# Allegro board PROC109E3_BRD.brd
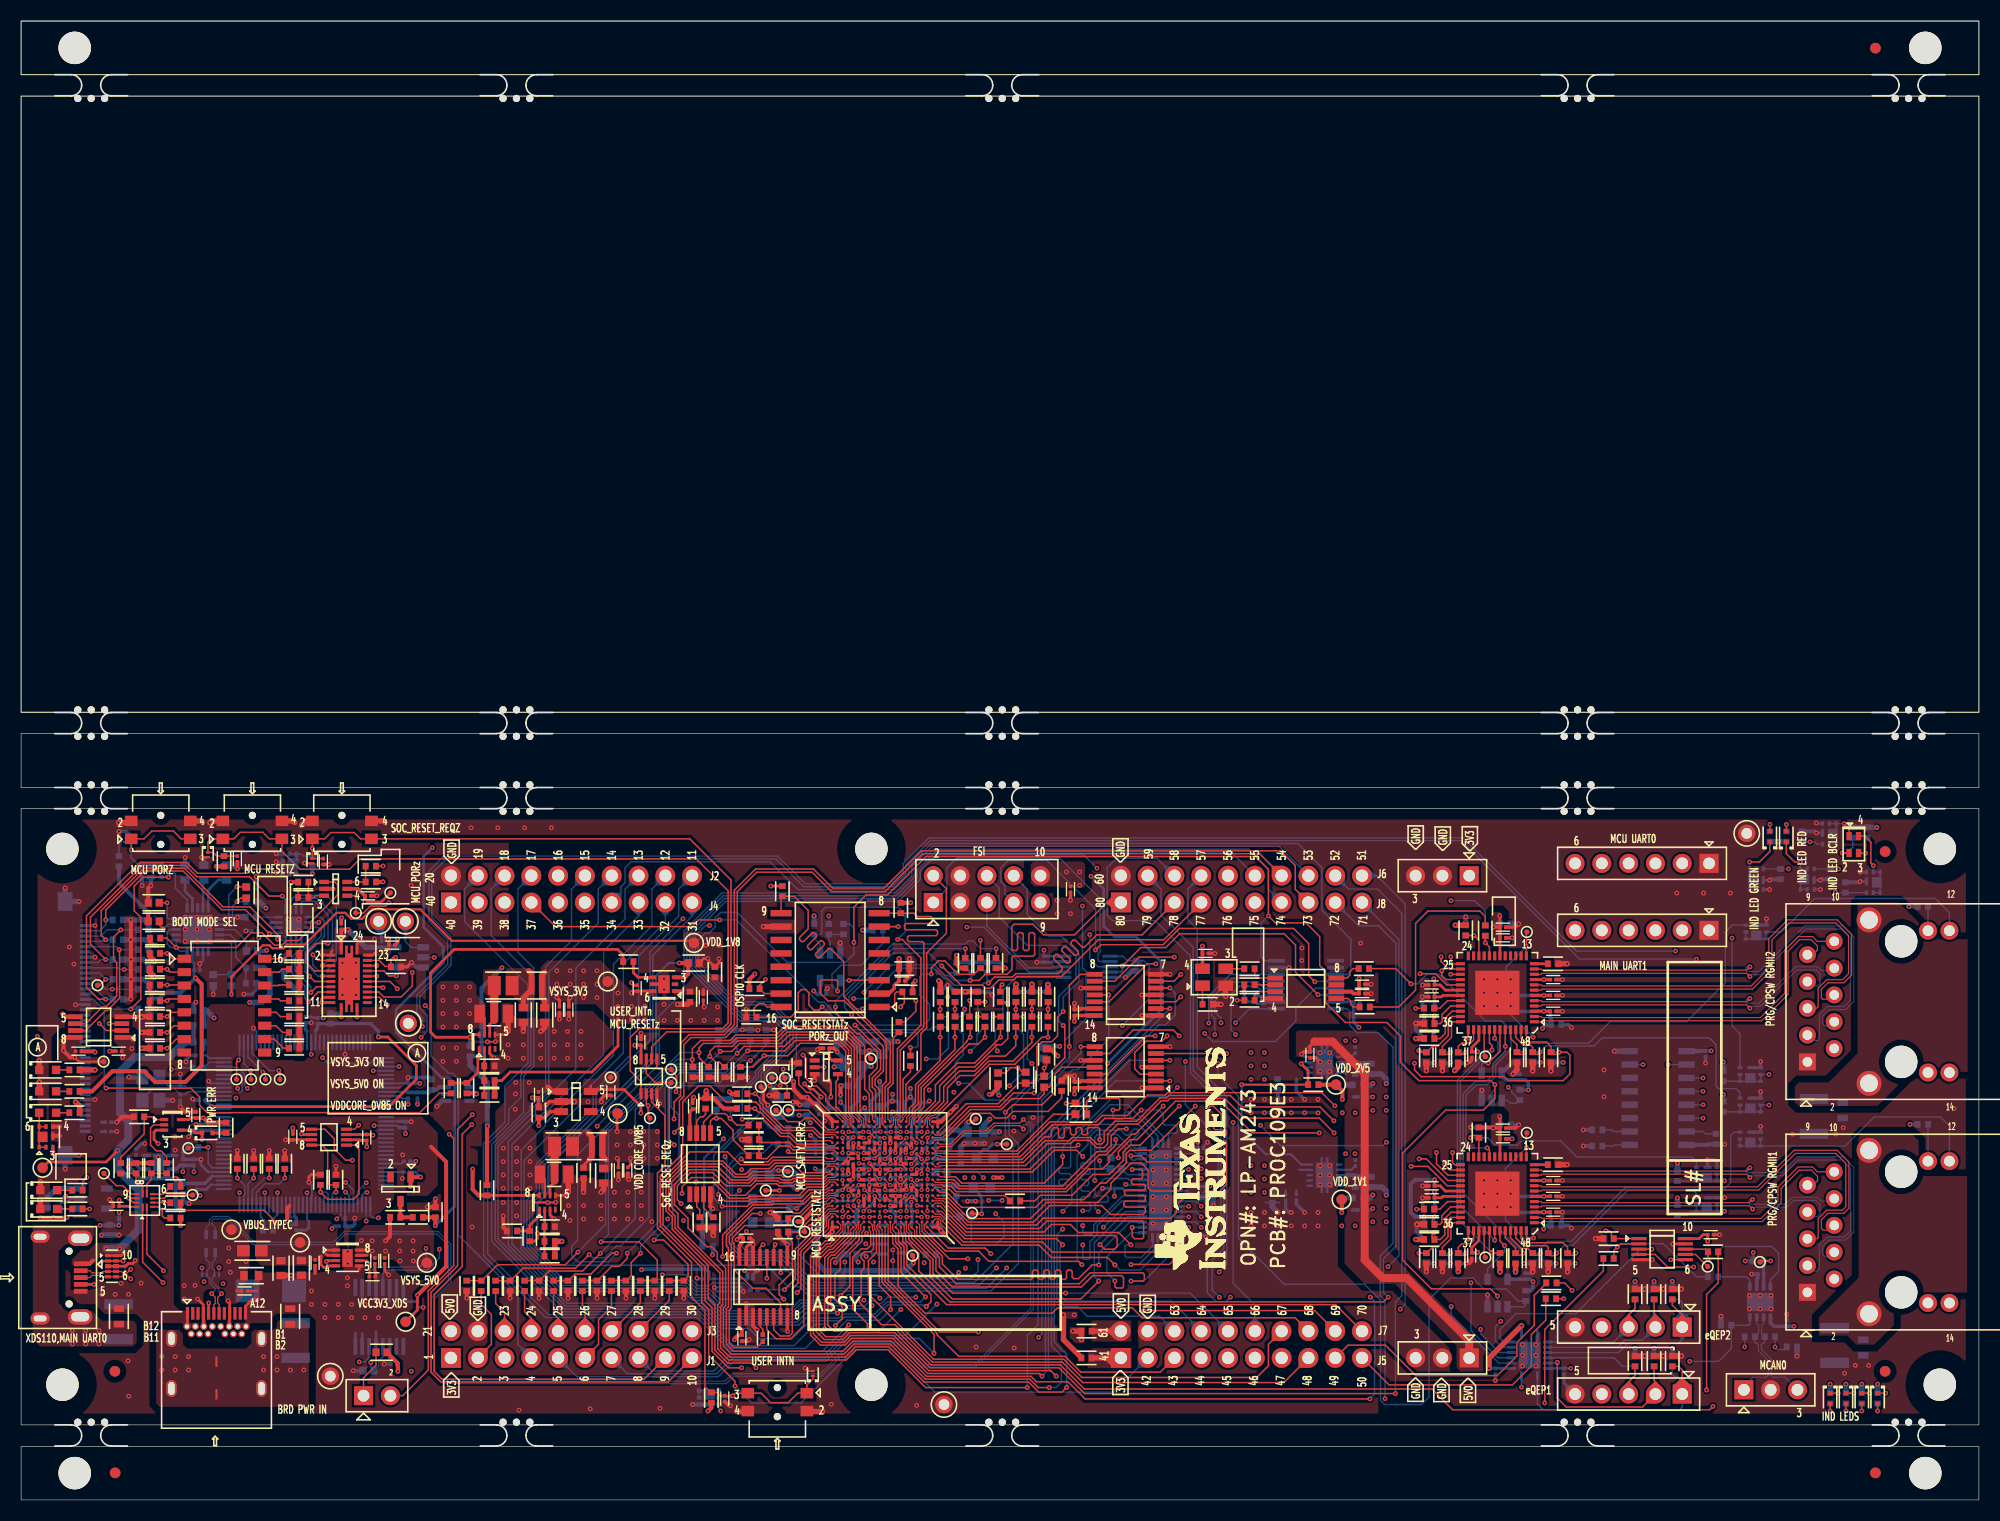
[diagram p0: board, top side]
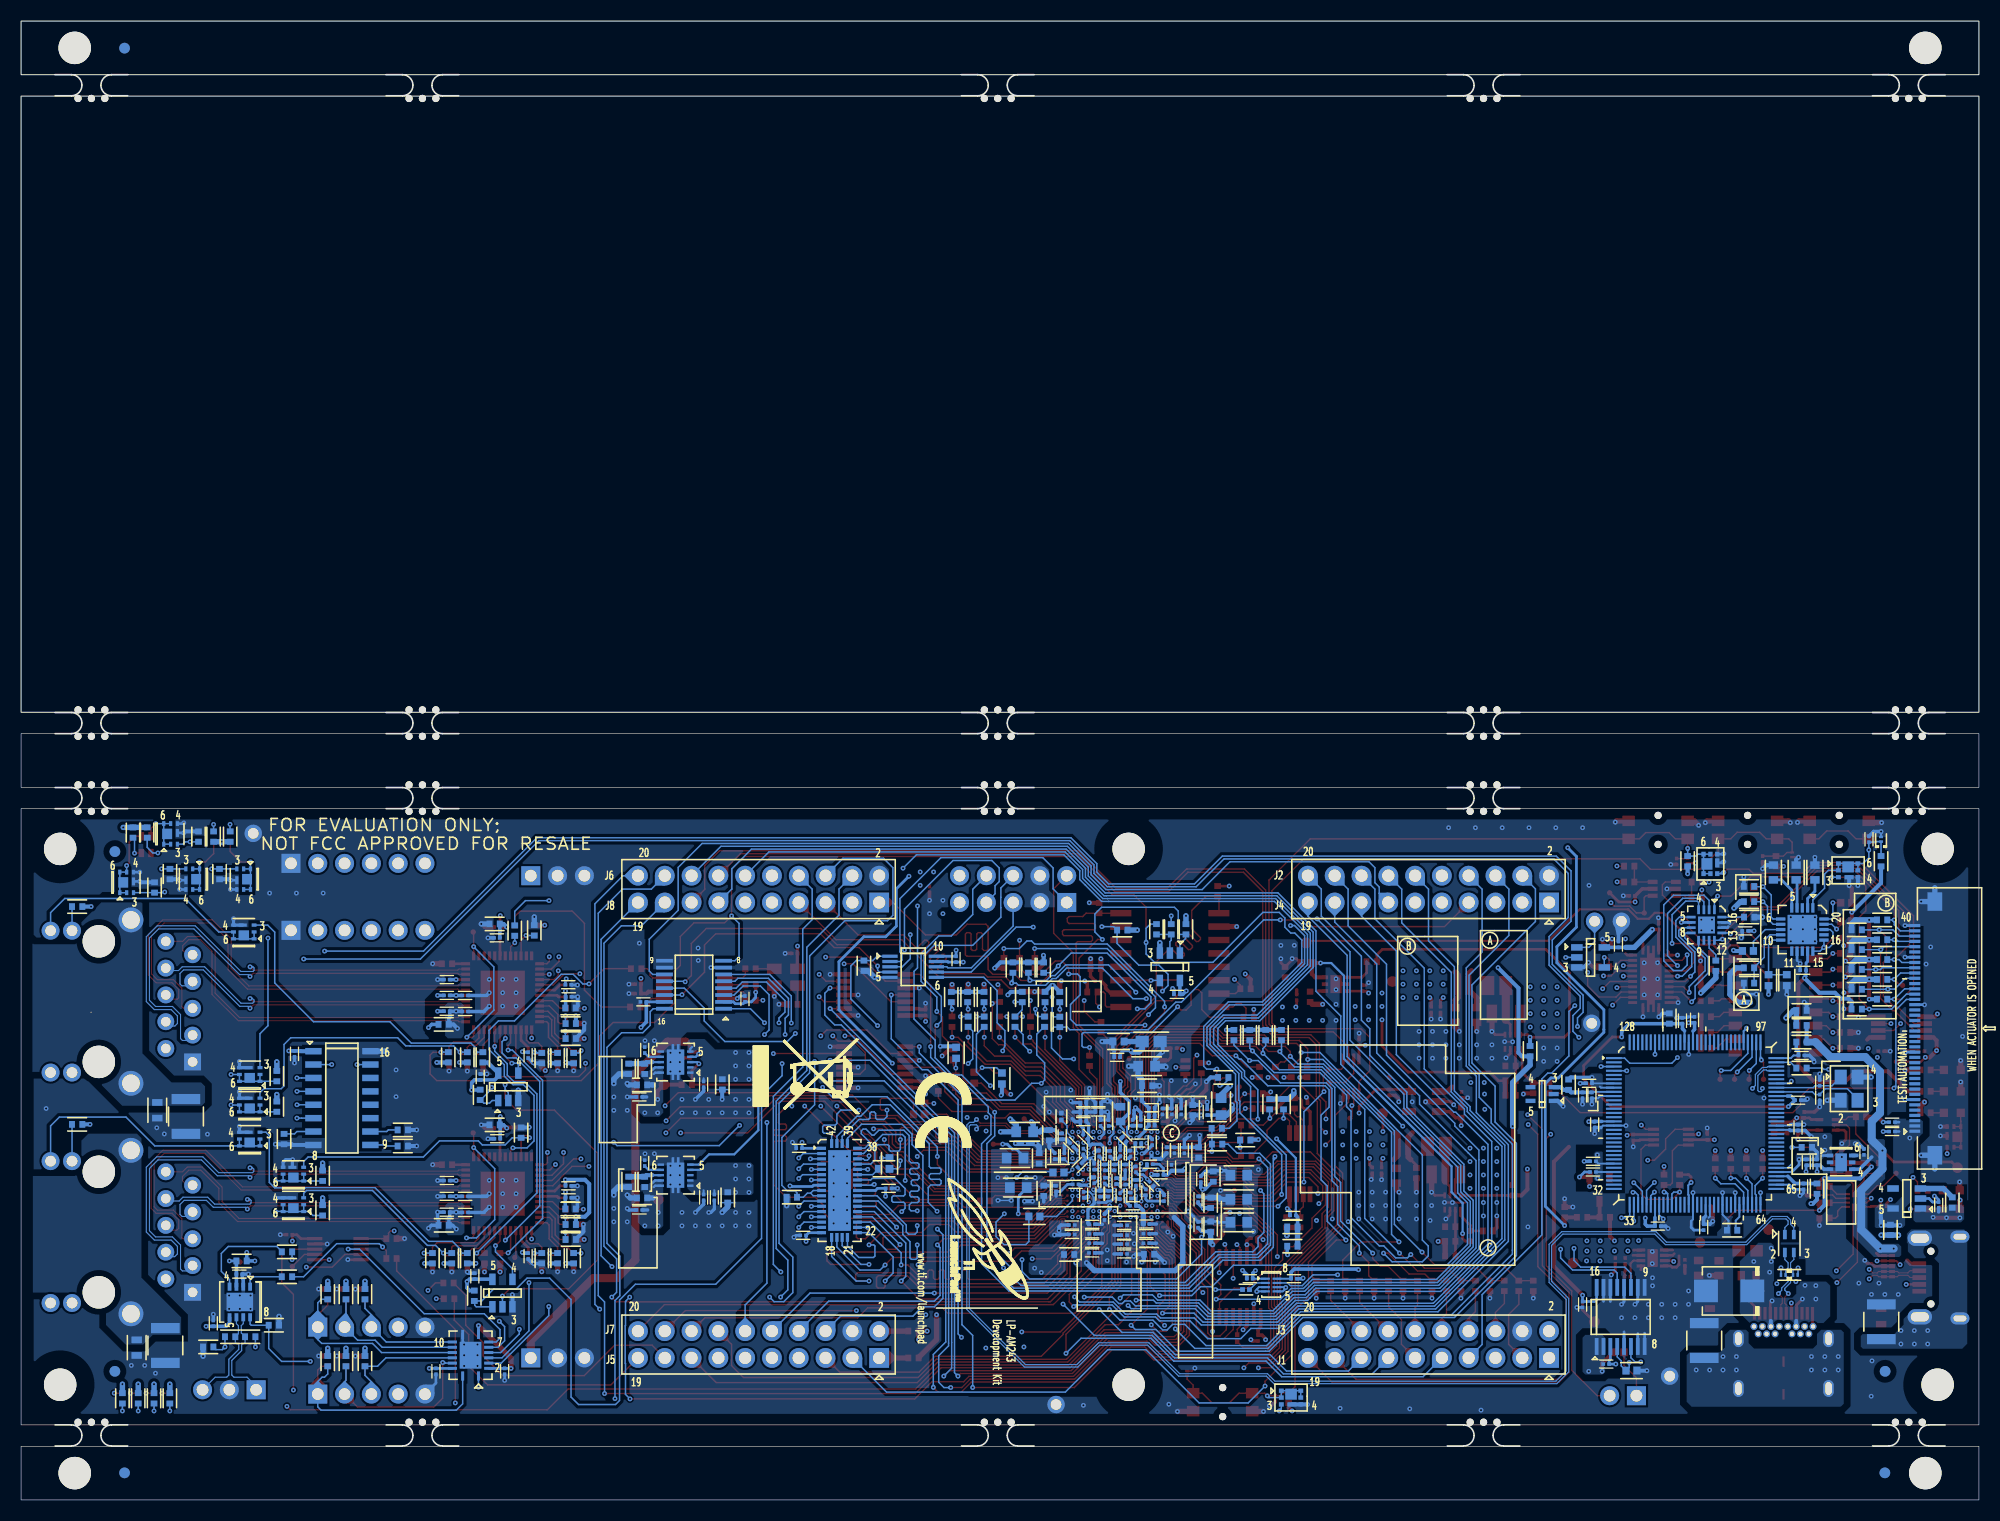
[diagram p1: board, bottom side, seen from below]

Outline 185.58 x 140.21 mm; copper layers: TOP, L02_GND1, L03_SIG1, L04_PWR1, L05_GND2, BOTTOM. Coordinates in mm from the lower left corner of the outline.
Outline path: rectangle 0,135.13 185.58,140.21 ; rectangle 0,74.68 185.58,133.1 ; 0,72.64 0,67.56 185.58,67.56 185.58,72.64 0,72.64 ; 0,65.53 0,7.11 185.58,7.11 185.58,65.53 0,65.53 ; 0,5.08 0,0 185.58,0 185.58,5.08 0,5.08

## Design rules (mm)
net group MCAN0_HL: nets MCAN0_H MCAN0_L
net group PRG1_CPSW_RGMII2_RX: nets PRG1_CPSW_RGMII2_RD0 PRG1_CPSW_RGMII2_RD1
net group TYPEC_DP: nets TYPEC_DN TYPEC_DP
net group USB0: nets USB0_DN USB0_DP
net group XDS_USB_D_NP: nets XDS_USB_D_N XDS_USB_D_P
net group CPSW_RGMII1_TD1: nets CPSW_RGMII1_TD1
net group CPSW_RGMII1_TX_CTL: nets CPSW_RGMII1_TX_CTL
net group PRG1_CPSW RGMII2_TX: nets PRG1_CPSW_RGMII2_TD0 PRG1_CPSW_RGMII2_TD1 PRG1_CPSW_RGMII2_TD2 PRG1_CPSW_RGMII2_TD3 PRG1_CPSW_RGMII2_TX_CTL
net group PRG1_CPSW_RGMII1_RXC: nets PRG1_CPSW_RGMII1_RXC
net group PRG1_CPSW_RGMII2_RXC: nets PRG1_CPSW_RGMII2_RXC
net group PRG1_CPSW_RGMII2_TXC: nets PRG1_CPSW_RGMII2_TXC
net group PWR\GND: nets VBAT_XDS VCC_5V0_CAN VDD_1V1_SS VDD_1V8_R VDD_2V5_PG VDD_CORE_0V85_R VDDA_3V3 VDDA_PLL0 VDDC_1V2_XDS VDDSHV_SDIO VMON_VSYS VSYS_3V3_R XDS_VREF

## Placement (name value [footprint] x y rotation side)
C1  1uF  [CAP0201_0-5]  20.5 60.76 270 top
C2  1uF  [CAP0201_0-5]  28.65 60.53 270 top
C3  0.1uF  [CAP0201_0-5]  99.47 57.89 90 top
C4  0.1uF  [CAP0201_0-5]  32.87 57.28 0 top
C5  0.1uF  [CAP0201_0-5]  30.34 54.36 90 top
C6  0.1uF  [CAP0201_0-5]  140.46 54.31 0 top
C7  0.1uF  [CAP0201_0-5]  140.46 53.29 0 top
C8  0.1uF  [CAP0201_0-5]  35.15 52.6 0 top
C9  0.1uF  [CAP0201_0-5]  112.26 51.82 180 top
C10  4.7uF  [CAP0402_0-75]  83.72 50.37 0 top
C11  0.1uF  [CAP0201_0-5]  145.23 49.33 0 top
C12  0.1uF  [CAP0201_0-5]  83.49 49.2 0 top
C13  1uF  [CAP0201_0-5]  127.11 48.9 0 top
C14  0.01uF  [CAP0201_0-5]  133.7 48.83 180 top
C15  1uF  [CAP0201_0-5]  58.4 48.51 90 top
C16  0.1uF  [CAP0201_0-5]  127.11 48.01 180 top
C17  0.01uF  [CAP0201_0-5]  145.23 47.83 0 top
C18  2.2uF  [CAP0402_0-75]  63.4 47.7 270 top
C19  0.1uF  [CAP0201_0-5]  133.7 47.69 180 top
C20  0.1uF  [CAP0201_0-5]  64.67 47.65 270 top
C21  0.1uF  [CAP0201_0-5]  51.03 46.48 270 top
C22  0.1uF  [CAP0201_0-5]  51.92 46.48 270 top
C23  0.01uF  [CAP0201_0-5]  145.23 46.33 0 top
C24  0.1uF  [CAP0201_0-5]  99.84 46.21 90 top
C25  4.7uF  [CAP1206_2]  44.81 46.1 0 top
C26  22uF  [CAP0603_1]  47.6 45.97 270 top
C27  47uF  [CAP0603_1]  49.64 45.97 270 top
C28  100pF  [CAP0402_0-75]  63.68 40.56 270 top
C29  0.1uF  [CAP0201_0-5]  58.75 43.38 90 top
C30  0.1uF  [CAP0201_0-5]  76.33 42.82 0 top
C31  0.1uF  [CAP0201_0-5]  5.44 42.55 0 top
C32  0.1uF  [CAP0201_0-5]  9.25 42.55 180 top
C33  100pF  [CAP0402_0-75]  65.18 40.56 270 top
C34  0.1uF  [CAP0201_0-5]  137.51 42.22 270 top
C35  100pF  [CAP0402_0-75]  66.69 40.56 270 top
C36  100pF  [CAP0402_0-75]  68.19 40.56 270 top
C37  0.1uF  [CAP0201_0-5]  99.84 39.35 90 top
C38  1uF  [CAP0201_0-5]  55.91 38.63 270 top
C39  1uF  [CAP0201_0-5]  49.05 38.4 270 top
C40  120pF  [CAP0402_0-75]  44.39 38.35 180 top
C41  0.1uF  [CAP0201_0-5]  63.65 37.34 90 top
C42  0.1uF  [CAP0201_0-5]  16.56 36.5 90 top
C43  0.1uF  [CAP0201_0-5]  140.46 35.26 0 top
C44  0.1uF  [CAP0201_0-5]  25.76 34.42 90 top
C45  0.1uF  [CAP0201_0-5]  32.77 34.36 270 top
C46  0.1uF  [CAP0201_0-5]  140.46 34.24 0 top
C47  10pF  [CAP0402_0-75]  69.45 34.16 180 top
C48  0.1uF  [CAP0201_0-5]  56.62 31.24 270 top
C49  0.1uF  [CAP0201_0-5]  57.51 31.24 270 top
C50  10uF  [CAP0402_0-75]  53.32 30.99 270 top
C51  4.7uF  [CAP1206_2]  50.53 30.86 0 top
C52  47uF  [CAP0603_1]  55.22 30.73 270 top
C53  0.1uF  [CAP0201_0-5]  145.23 30.28 0 top
C54  0.01uF  [CAP0201_0-5]  133.7 29.78 180 top
C55  0.01uF  [CAP0201_0-5]  145.23 28.78 0 top
C56  0.1uF  [CAP0201_0-5]  133.7 28.64 180 top
C57  0.1uF  [CAP0201_0-5]  9.02 27.84 180 top
C58  0.01uF  [CAP0201_0-5]  145.23 27.28 0 top
C59  0.1uF  [CAP0201_0-5]  160.15 25.15 0 top
C60  0.1uF  [CAP0201_0-5]  68.73 24.82 0 top
C61  0.1uF  [CAP0201_0-5]  137.51 23.17 270 top
C62  120pF  [CAP0402_0-75]  50.11 23.11 180 top
C63  0.1uF  [CAP0201_0-5]  33.53 22.66 270 top
C64  1uF  [CAP0201_0-5]  34.47 22.66 270 top
C65  0.1uF  [CAP0201_0-5]  27.86 22.48 270 top
C66  10uF  [CAP0603_1]  26.57 22 270 top
C67  10uF  [CAP0603_1]  24.64 21.97 270 top
C68  10uF  [CAP0603_1]  21.82 21.26 0 top
C69  0.01uF  [CAP0201_0-5]  33.3 21.16 0 top
C70  0.1uF  [CAP0201_0-5]  21.19 19.81 0 top
C71  1000pF  [CAP0402_0-75]  152.98 19.51 90 top
C72  1000pF  [CAP0402_0-75]  154.79 19.51 90 top
C73  1000pF  [CAP0402_0-75]  156.51 19.51 90 top
C74  0.1uF  [CAP0201_0-5]  68.33 15.34 270 top
C75  1000pF  [CAP0402_0-75]  152.98 13.16 90 top
C76  1000pF  [CAP0402_0-75]  154.79 13.16 90 top
C77  1000pF  [CAP0402_0-75]  156.51 13.16 90 top
C78  1uF  [CAP0201_0-5]  66.7 9.61 270 top
C79  1uF  [CAP0201_0-5]  10.42 62.64 90 bottom
C80  2400pF  [CAP0603_1]  19.48 59.49 90 bottom
C81  2400pF  [CAP0603_1]  17.32 59.49 90 bottom
C82  2400pF  [CAP0603_1]  15.54 59.49 90 bottom
C84  10uF  [CAP0402_0-75]  140.7 54.61 0 bottom
C85  0.1uF  [CAP0201_0-5]  22.15 53.95 180 bottom
C86  1uF  [CAP0201_0-5]  140.49 53.29 0 bottom
C88  0.1uF  [CAP0201_0-5]  34.17 52.66 90 bottom
C90  0.1uF  [CAP0201_0-5]  96.96 51.27 270 bottom
C91  0.1uF  [CAP0201_0-5]  16.66 50.22 0 bottom
C92  0.1uF  [CAP0201_0-5]  145.23 49.33 0 bottom
C93  1uF  [CAP0201_0-5]  133.71 48.84 180 bottom
C94  0.1uF  [CAP0201_0-5]  76.02 47.93 0 bottom
C95  0.1uF  [CAP0201_0-5]  145.23 47.83 0 bottom
C96  1uF  [CAP0201_0-5]  143.49 47.83 180 bottom
C97  1uF  [CAP0201_0-5]  133.68 47.7 180 bottom
C98  10uF  [CAP0402_0-75]  133.51 46.63 180 bottom
C99  1uF  [CAP0201_0-5]  145.23 46.33 0 bottom
C100  1uF  [CAP0201_0-5]  143.49 46.3 180 bottom
C101  1000pF  [CAP1210_1-5]  169.95 36.36 270 bottom
C102  2.2uF  [CAP0402_0-75]  29.34 45.64 90 bottom
C103  0.1uF  [CAP0201_0-5]  116.97 47.5 90 bottom
C104  0.1uF  [CAP0201_0-5]  26.95 45.52 90 bottom
C105  0.01uF  [CAP0201_0-5]  28.1 45.43 90 bottom
C106  0.1uF  [CAP0201_0-5]  126.59 47.22 0 bottom
C107  10uF  [CAP0402_0-75]  145.52 45.09 0 bottom
C108  100pF  [CAP0402_0-75]  66.11 44.07 90 bottom
C109  4.7uF  [CAP0402_0-75]  81.56 43.46 0 bottom
C110  100pF  [CAP0402_0-75]  67.61 44.07 90 bottom
C111  0.01uF  [CAP0201_0-5]  126.47 42.65 90 bottom
C112  0.1uF  [CAP0201_0-5]  159.66 42.29 90 bottom
C113  1uF  [CAP0201_0-5]  137.52 42.16 270 bottom
C114  0.1uF  [CAP0201_0-5]  16.82 42.14 180 bottom
C116  0.01uF  [CAP0201_0-5]  81.69 41.96 0 bottom
C117  100pF  [CAP0402_0-75]  69.11 44.07 90 bottom
C118  100pF  [CAP0402_0-75]  70.62 44.07 90 bottom
C119  0.1uF  [CAP0201_0-5]  142.06 40.11 90 bottom
C120  30pF  [CAP0201_0-5]  15.09 39.55 270 bottom
C121  0.1uF  [CAP0201_0-5]  36.96 39.5 0 bottom
C122  0.1uF  [CAP0201_0-5]  120.88 39.4 270 bottom
C123  1uF  [CAP0201_0-5]  122.17 42.19 270 top
C124  4.7uF  [CAP0402_0-75]  119.11 39.4 270 bottom
C125  10uF  [CAP0402_0-75]  126.72 39.35 0 bottom
C126  4.7uF  [CAP0402_0-75]  78.84 39.27 180 bottom
C128  0.01uF  [CAP0201_0-5]  37.57 38.35 270 bottom
C129  0.1uF  [CAP0201_0-5]  36.68 38.35 270 bottom
C130  0.1uF  [CAP0201_0-5]  126.97 38.21 0 bottom
C131  30pF  [CAP0201_0-5]  15.09 38.15 90 bottom
C132  1uF  [CAP0201_0-5]  17.14 37.9 180 bottom
C133  0.1uF  [CAP0201_0-5]  84.89 37.67 0 bottom
C134  0.1uF  [CAP0201_0-5]  83.47 37.67 180 bottom
C135  0.1uF  [CAP0201_0-5]  78.41 37.19 180 bottom
C136  10uF  [CAP0402_0-75]  74.52 36.96 90 bottom
C137  0.1uF  [CAP0201_0-5]  77.39 36.83 90 bottom
C138  0.1uF  [CAP0201_0-5]  76.5 36.83 90 bottom
C139  0.1uF  [CAP0201_0-5]  75.62 36.83 90 bottom
C140  0.1uF  [CAP0201_0-5]  84.89 36.78 0 bottom
C141  0.1uF  [CAP0201_0-5]  83.47 36.78 180 bottom
C142  0.1uF  [CAP0201_0-5]  73.15 36.77 90 bottom
C143  3.3uF  [CAP0603_1]  81.36 36.58 90 bottom
C144  0.1uF  [CAP0201_0-5]  78.41 36.42 180 bottom
C145  0.1uF  [CAP0201_0-5]  84.89 35.86 0 bottom
C146  0.1uF  [CAP0201_0-5]  8.23 35.81 0 bottom
C147  0.1uF  [CAP0201_0-5]  80.21 35.76 90 bottom
C148  0.01uF  [CAP0201_0-5]  79.45 35.76 90 bottom
C149  1uF  [CAP0201_0-5]  83.26 35.74 90 bottom
C150  1uF  [CAP0201_0-5]  82.5 35.74 90 bottom
C151  0.01uF  [CAP0201_0-5]  36.42 35.59 270 bottom
C152  10uF  [CAP0402_0-75]  140.7 35.56 0 bottom
C153  0.01uF  [CAP0201_0-5]  78.41 35.48 180 bottom
C154  1uF  [CAP0201_0-5]  17.14 35.31 90 bottom
C155  0.1uF  [CAP0201_0-5]  8.23 34.92 0 bottom
C156  4.7uF  [CAP0402_0-75]  88.11 34.57 270 bottom
C157  0.1uF  [CAP0201_0-5]  86.89 34.47 270 bottom
C158  0.1uF  [CAP0201_0-5]  84.71 34.42 45 bottom
C159  1uF  [CAP0201_0-5]  140.44 34.24 0 bottom
C160  0.1uF  [CAP0201_0-5]  81 34.19 225 bottom
C161  10pF  [CAP0402_0-75]  69.55 34.11 180 bottom
C162  0.1uF  [CAP0201_0-5]  78.36 33.91 90 bottom
C163  0.1uF  [CAP0201_0-5]  79.68 33.83 180 bottom
C165  0.1uF  [CAP0201_0-5]  86.03 33.68 45 bottom
C166  0.1uF  [CAP0201_0-5]  111.83 33.34 0 bottom
C167  0.1uF  [CAP0201_0-5]  77.01 33.15 90 bottom
C168  0.1uF  [CAP0201_0-5]  76.26 33.15 90 bottom
C169  0.1uF  [CAP0201_0-5]  75.32 33.15 90 bottom
C170  1uF  [CAP0201_0-5]  10.9 32.99 90 bottom
C171  4.7uF  [CAP0402_0-75]  73.97 32.94 90 bottom
C172  0.1uF  [CAP0201_0-5]  81.39 32.87 270 bottom
C173  1uF  [CAP0201_0-5]  83.39 32.84 270 bottom
C174  0.01uF  [CAP0201_0-5]  80.42 32.84 90 bottom
C175  0.1uF  [CAP0201_0-5]  82.35 32.82 270 bottom
C176  0.1uF  [CAP0201_0-5]  87.6 32.59 90 bottom
C177  0.01uF  [CAP0201_0-5]  86.69 32.59 90 bottom
C178  0.01uF  [CAP0201_0-5]  84.89 33.02 270 bottom
C179  4.7uF  [CAP0402_0-75]  89.08 32.38 90 bottom
C180  1uF  [CAP0201_0-5]  36.58 32.11 0 bottom
C181  0.1uF  [CAP0201_0-5]  16.36 32 270 bottom
C182  1uF  [CAP0201_0-5]  15.35 32 270 bottom
C183  0.01uF  [CAP0201_0-5]  126.47 31.93 90 bottom
C184  0.01uF  [CAP0201_0-5]  78.59 31.83 180 bottom
C185  0.01uF  [CAP0201_0-5]  83.87 31.6 90 bottom
C186  0.1uF  [CAP0201_0-5]  82.87 31.52 270 bottom
C187  1uF  [CAP0201_0-5]  81.92 31.52 270 bottom
C188  0.01uF  [CAP0201_0-5]  80.91 31.52 270 bottom
C189  0.1uF  [CAP0201_0-5]  76.53 31.5 270 bottom
C190  0.01uF  [CAP0201_0-5]  79.91 31.34 270 bottom
C191  0.01uF  [CAP0201_0-5]  36.58 31.09 0 bottom
C192  1uF  [CAP0201_0-5]  77.57 30.82 180 bottom
C193  4.7uF  [CAP0402_0-75]  72.57 30.66 270 bottom
C194  0.1uF  [CAP0201_0-5]  73.76 30.4 270 bottom
C196  1uF  [CAP0201_0-5]  83.86 30.3 270 bottom
C197  0.1uF  [CAP0201_0-5]  145.23 30.28 0 bottom
C198  0.01uF  [CAP0201_0-5]  82.85 30.28 270 bottom
C199  0.1uF  [CAP0201_0-5]  81.79 30.23 90 bottom
C200  0.01uF  [CAP0201_0-5]  80.92 30.18 90 bottom
C201  0.1uF  [CAP0201_0-5]  79.91 30.06 270 bottom
C202  0.1uF  [CAP0201_0-5]  78.41 29.97 45 bottom
C203  0.01uF  [CAP0201_0-5]  85.62 29.92 0 bottom
C204  0.1uF  [CAP0201_0-5]  87.48 29.51 270 bottom
C205  0.1uF  [CAP0201_0-5]  85.24 31.75 135 bottom
C206  4.7uF  [CAP0402_0-75]  88.65 29.31 270 bottom
C207  1uF  [CAP0201_0-5]  133.7 29.78 180 bottom
C208  0.1uF  [CAP0201_0-5]  16.62 29.72 270 bottom
C209  0.1uF  [CAP0201_0-5]  103.35 29.54 180 bottom
C210  0.01uF  [CAP0201_0-5]  78.97 29.16 270 bottom
C211  0.1uF  [CAP0201_0-5]  83.32 29.03 270 bottom
C212  0.1uF  [CAP0201_0-5]  82.5 29.03 270 bottom
C213  0.1uF  [CAP0201_0-5]  84.86 28.93 270 bottom
C214  0.1uF  [CAP0201_0-5]  80.39 28.85 90 bottom
C215  0.1uF  [CAP0201_0-5]  81.41 28.8 90 bottom
C216  0.1uF  [CAP0201_0-5]  145.23 28.78 0 bottom
C217  1uF  [CAP0201_0-5]  143.49 28.78 180 bottom
C218  0.1uF  [CAP0201_0-5]  120.88 28.68 270 bottom
C219  1uF  [CAP0201_0-5]  119.87 28.68 270 bottom
C220  4.7uF  [CAP0402_0-75]  118.6 28.68 270 bottom
C221  1uF  [CAP0201_0-5]  133.7 28.64 180 bottom
C222  10uF  [CAP0402_0-75]  126.72 28.63 0 bottom
C223  1uF  [CAP0201_0-5]  77.24 28.6 270 bottom
C224  0.1uF  [CAP0201_0-5]  74.02 28.5 270 bottom
C225  4.7uF  [CAP0402_0-75]  72.82 28.17 270 bottom
C226  1uF  [CAP0201_0-5]  3.81 27.96 90 bottom
C227  0.1uF  [CAP0201_0-5]  80.19 27.89 0 bottom
C228  10uF  [CAP0402_0-75]  133.51 27.58 180 bottom
C229  0.1uF  [CAP0201_0-5]  126.97 27.49 0 bottom
C230  1uF  [CAP0201_0-5]  145.23 27.28 0 bottom
C231  1uF  [CAP0201_0-5]  143.49 27.25 180 bottom
C232  0.1uF  [CAP0201_0-5]  65.02 26.97 0 bottom
C233  1uF  [CAP0201_0-5]  82.88 26.82 270 bottom
C234  0.01uF  [CAP0201_0-5]  78.92 26.16 180 bottom
C235  0.1uF  [CAP0201_0-5]  84.05 26.13 180 bottom
C236  0.1uF  [CAP0201_0-5]  74.02 26.09 270 bottom
C237  0.1uF  [CAP0201_0-5]  85.98 26.06 0 bottom
C238  10uF  [CAP0402_0-75]  145.52 26.03 0 bottom
C239  0.1uF  [CAP0201_0-5]  81.03 26.03 0 bottom
C240  0.01uF  [CAP0201_0-5]  30.43 25.96 180 bottom
C241  4.7uF  [CAP0402_0-75]  72.82 25.91 270 bottom
C242  0.01uF  [CAP0201_0-5]  26.09 25.86 270 bottom
C243  10uF  [CAP0402_0-75]  8.38 25.6 270 bottom
C244  0.1uF  [CAP0201_0-5]  78.92 25.24 180 bottom
C245  0.1uF  [CAP0201_0-5]  84.05 25.22 180 bottom
C246  0.1uF  [CAP0201_0-5]  85.98 25.17 0 bottom
C247  0.1uF  [CAP0201_0-5]  81.03 25.1 0 bottom
C248  0.1uF  [CAP0201_0-5]  111.45 25.08 0 bottom
C249  0.1uF  [CAP0201_0-5]  84.05 24.33 180 bottom
C250  0.1uF  [CAP0201_0-5]  78.92 24.33 180 bottom
C251  0.1uF  [CAP0201_0-5]  81.03 24.26 0 bottom
C252  1000pF  [CAP1210_1-5]  171.91 14.64 270 bottom
C253  0.01uF  [CAP0201_0-5]  84.07 23.42 180 bottom
C254  0.1uF  [CAP0201_0-5]  81.03 23.32 0 bottom
C255  4.7uF  [CAP0402_0-75]  78.66 23.29 180 bottom
C256  1uF  [CAP0201_0-5]  137.52 23.11 270 bottom
C257  0.1uF  [CAP0201_0-5]  164.89 21.41 180 bottom
C258  0.1uF  [CAP0201_0-5]  142.57 21.21 90 bottom
C259  0.1uF  [CAP0201_0-5]  69.11 20.97 0 bottom
C260  0.1uF  [CAP0201_0-5]  64.92 20.97 180 bottom
C262  0.1uF  [CAP0201_0-5]  37.57 18.53 270 bottom
C263  1000pF  [CAP1210_1-5]  9.25 16.89 90 bottom
C265  0.1uF  [CAP0201_0-5]  167.36 16.74 270 bottom
C266  1000pF  [CAP1210_1-5]  26.04 15.11 90 bottom
C267  4700pF  [CAP0402_0-75]  167.84 14.5 0 bottom
C268  0.1uF  [CAP0201_0-5]  35.33 12.88 180 bottom
C269  0.1uF  [CAP0201_0-5]  146.26 12.19 270 bottom
C270  0.1uF  [CAP0201_0-5]  139.75 12.19 270 bottom
D1  TPD1E01B04DPLT  [DIO_DFN0201_0-4]  17.7 61.16 270 top
D2  TPD1E01B04DPLT  [DIO_DFN0201_0-4]  27.61 60.58 270 top
D3  BZX84C6V8LT1G  [SOT23-123_1-2]  35.97 29.46 270 top
D4  TPD1E01B04DPLT  [DIO_DFN0201_0-4]  75.05 11.99 90 top
D5  TPD1E01B04DPLT  [DIO_DFN0201_0-4]  9.28 62.64 90 bottom
D6  TPD1E01B04DPLT  [DIO_DFN0201_0-4]  18.54 21.34 0 bottom
D7  TPD1E01B04DPLT  [DIO_DFN0201_0-4]  17.4 21.34 180 bottom
D8  SMBJ6.5CA  [DIO_SMB_2-7]  23.67 19.81 0 bottom
FB1  120E  [IND0603_1#2]  78.46 43.46 0 bottom
FB2  120E  [IND0603_1]  78.89 41.12 0 bottom
FB3  120E  [IND0603_1]  71.83 37.29 270 bottom
FB4  120E  [IND0603_1]  90.45 34.9 180 bottom
FB5  120E  [IND0603_1]  91.36 32.41 180 bottom
FB6  120E  [IND0603_1]  70.15 30.78 0 bottom
FB7  120E  [IND0603_1]  91.06 29.62 180 bottom
FB8  120E  [IND0603_1]  70.15 28.5 0 bottom
FB9  120E  [IND0603_1]  70.15 26.31 0 bottom
FL1  70E  [EMIFIL_BLM18B_0603_0-7]  21.92 23.62 0 top
J1  RECP_2X10  [RECPT_2X10_CRD-081413-A_S_T_8-6]  40.75 13.46 0 bottom
J2  RECP_2X10  [RECPT_2X10_CRD-081413-A_S_T_8-6]  40.75 56.64 0 bottom
J5  RECP_2X10  [RECPT_2X10_CRD-081413-A_S_T_8-6]  104.25 13.46 0 bottom
J6  RECP_2X10  [RECPT_2X10_CRD-081413-A_S_T_8-6]  104.25 56.64 0 bottom
J9  HDR_1X3  [HDR_1X3_100_S_T]  137.27 13.46 0 top
J10  CON_USB-C_24_F  [CON_USBC24_6327233_S_R_S_3-1]  18.52 11.88 0 top
J11  HDR_1X3  [HDR_1X3_100_S_T]  163.3 10.44 180 top
J12  HDR_1X5  [HDR_1X5_61300511121_S_T_8-6]  157.46 10.03 0 top
J13  HDR_1X6  [HDR_1X6_61300611121_S_T_8-6]  160 54 0 top
J14  HDR_1X3  [HDR_1X3_100_S_T]  137.27 59.18 0 top
J15  CON_FLEX_1X40_687140183622  [CON_FLEX1X40_687140183622_S_R_S_1-3]  3.67 44.7 90 bottom
J16  HDR_2X5  [HDR_2X5_61301021121_S_T_8-6]  86.47 56.64 0 top
J17  HDR_1X6  [HDR_1X6_61300611121_S_T_8-6]  160 60.35 0 top
J18  CON_RJ45-14_LPJG16314A4NL  [CON_RJ45-14_LPJG16314A4NL_S_R_T_13-6]  169.32 41.53 90 top
J19  CON_RJ45-14_LPJG16314A4NL  [CON_RJ45-14_LPJG16314A4NL_S_R_T_13-6]  169.32 19.68 90 top
J20  CON_MUSB-B_5_F  [CON_MUSBB5_629105150521_S_R_S_2-7]  2.7 21.08 270 top
J21  HDR_1X5  [HDR_1X5_61300511121_S_T_8-6]  157.46 16.38 0 top
J22  HDR_1X2  [HDR_1X2_61300211121_S_T_8-6]  32.46 9.88 180 top
L1  0.47uH  [IND0806_1-2]  45.7 48.77 0 top
L2  0.47uH  [IND0806_1-2]  51.41 33.53 0 top
L3  90E  [IND4_DLW21H_90X60_SMD_1-4]  17.97 24.31 270 bottom
LD1  150040VS73220  [LED_150040GS73220_40X20_SMD_0-4]  167.32 62.89 90 top
LD2  150040RS73220  [LED_150040GS73220_40X20_SMD_0-4]  165.76 62.9 90 top
LD3  150066RV54050  [LED4_150066RV54050_70X60_SMD_0-7]  173.72 62.13 270 top
LD6  150060VS75000  [LED_150060SS75000_70X40_SMD_0-8]  2.52 40.77 0 top
LD7  150060VS75000  [LED_150060SS75000_70X40_SMD_0-8]  2.52 38.73 0 top
LD8  150060VS75000  [LED_150060SS75000_70X40_SMD_0-8]  2.52 36.7 0 top
LD9  150040RS73220  [LED_150040GS73220_40X20_SMD_0-4]  17.65 34.8 0 top
LD10  150060RS75000  [LED_150060SS75000_70X40_SMD_0-8]  2.62 29.36 0 top
LD11  150060VS75000  [LED_150060SS75000_70X40_SMD_0-8]  2.62 27.58 0 top
LD12  150040VS73220  [LED_150040GS73220_40X20_SMD_0-4]  171.48 9.62 270 top
LD13  150040VS73220  [LED_150040GS73220_40X20_SMD_0-4]  172.98 9.62 270 top
LD14  150040VS73220  [LED_150040GS73220_40X20_SMD_0-4]  174.48 9.62 270 top
LD15  150040VS73220  [LED_150040GS73220_40X20_SMD_0-4]  175.98 9.62 270 top
NOREF  -  []  -351.92 35.65 0 top
NOREF#2  -  [unnamed#2]  3.92 10.92 0 top
NOREF#3  -  [unnamed#3]  178.91 66.54 0 top
NOREF#4  -  [unnamed#2]  176.69 12.19 180 top
NOREF#5  -  [unnamed#4]  93 6.11 0 top
NOREF#6  -  [unnamed#2]  8.92 2.57 0 top
NOREF#7  -  [unnamed#4]  147.54 6.11 0 top
NOREF#8  -  [unnamed#2]  175.78 137.64 0 top
NOREF#9  -  [unnamed#4]  6.64 6.11 0 top
NOREF#10  -  []  0 72.64 90 top
NOREF#11  -  [unnamed#4]  46.95 134.13 180 top
NOREF#12  -  []  -345.01 -16.1 0 top
NOREF#13  -  [unnamed#2]  181.88 61.72 180 top
NOREF#14  -  [unnamed#3]  6.64 66.54 0 top
NOREF#15  -  []  0 7.11 0 top
NOREF#16  -  [unnamed#4]  93 134.13 180 top
NOREF#17  -  [unnamed#2]  5.08 137.67 180 top
NOREF#18  -  []  0 0 90 top
NOREF#19  -  [unnamed#3]  46.95 66.54 0 top
NOREF#20  -  []  0 67.56 90 top
NOREF#21  -  []  -357.68 338.2 0 top
NOREF#22  -  [unnamed#2]  80.6 61.72 180 top
NOREF#23  -  []  16.76 103.5 0 top
NOREF#24  -  [unnamed#4]  6.64 134.13 180 top
NOREF#25  -  [unnamed#2]  181.88 10.92 90 top
NOREF#26  -  [unnamed#2]  5.08 2.54 180 top
NOREF#27  -  [unnamed#2]  175.78 2.57 0 top
NOREF#28  -  [unnamed#2]  176.69 61.47 180 top
NOREF#29  -  [unnamed#4]  147.54 134.13 180 top
NOREF#30  -  [unnamed#4]  46.95 6.11 0 top
NOREF#31  -  [unnamed#3]  147.54 66.54 0 top
NOREF#32  -  [unnamed#3]  46.95 73.65 0 top
NOREF#33  -  []  0 7.11 90 top
NOREF#34  -  [unnamed#3]  6.64 73.65 180 top
NOREF#35  -  [unnamed#2]  80.6 10.92 90 top
NOREF#36  -  [unnamed#3]  93 73.65 0 top
NOREF#37  -  [unnamed#4]  178.91 134.13 180 top
NOREF#38  -  [unnamed#3]  178.91 73.65 0 top
NOREF#39  -  []  0 135.13 90 top
NOREF#40  -  [unnamed#3]  147.54 73.65 0 top
NOREF#41  -  [unnamed#2]  3.92 61.72 270 top
NOREF#42  -  [unnamed#2]  8.89 12.19 0 top
NOREF#43  -  []  88.62 -3.3 0 top
NOREF#44  -  [unnamed#2]  180.5 2.54 180 top
NOREF#45  -  [unnamed#3]  93 66.54 0 top
NOREF#46  -  [unnamed#4]  178.91 6.11 0 top
NOREF#47  -  [unnamed#2]  175.78 2.57 180 bottom
NOREF#48  -  [unnamed#2]  176.69 12.19 0 bottom
NOREF#49  -  [unnamed#2]  176.69 61.47 180 bottom
NOREF#50  -  [unnamed#2]  8.89 12.19 0 bottom
NOREF#51  -  [unnamed#2]  8.92 2.57 180 bottom
NOREF#52  -  [unnamed#2]  175.78 137.64 180 bottom
NOREF#53  -  [unnamed#2]  180.5 137.67 0 bottom
Q3  CSD16301Q2  [WSON6_CSD13202Q2_80X80_0-8]  2.36 34.42 90 top
Q4  CSD16301Q2  [WSON6_CSD13202Q2_80X80_0-8]  171.41 63.14 90 bottom
Q5  CSD16301Q2  [WSON6_CSD13202Q2_80X80_0-8]  164.49 58.85 270 bottom
Q6  CSD16301Q2  [WSON6_CSD13202Q2_80X80_0-8]  169.31 58.85 270 bottom
Q7  CSD25310Q2  [SON6_CSD17313Q2_80X80]  25.45 60.3 180 bottom
Q8  CSD25310Q2  [SON6_CSD17313Q2_80X80]  12.4 59.69 270 bottom
Q9  CSD16301Q2  [WSON6_CSD13202Q2_80X80_0-8]  175.58 58.55 90 bottom
Q10  CSD16301Q2  [WSON6_CSD13202Q2_80X80_0-8]  164.47 53.85 0 bottom
Q11  CSD16301Q2  [WSON6_CSD13202Q2_80X80_0-8]  163.91 37.44 0 bottom
Q12  CSD16301Q2  [WSON6_CSD13202Q2_80X80_0-8]  163.91 40.34 0 bottom
Q13  CSD16301Q2  [WSON6_CSD13202Q2_80X80_0-8]  163.91 34.21 0 bottom
Q14  CSD16301Q2  [WSON6_CSD13202Q2_80X80_0-8]  159.77 27.99 0 bottom
Q15  CSD16301Q2  [WSON6_CSD13202Q2_80X80_0-8]  159.77 30.89 0 bottom
Q16  CSD25310Q2  [SON6_CSD17313Q2_80X80]  65.2 9.7 270 bottom
R1  1K  [RES0402_0-5]  19.23 60.55 270 top
R2  0E  [RES0402_0-5]  33.15 60.09 180 top
R3  10K  [RES0402_0-5]  33.15 58.59 0 top
R4  10K  [RES0402_0-5]  26.75 58.57 180 top
R5  10K  [RES0402_0-5]  72.16 57.71 90 top
R6  12.7K_1%  [RES0402_0-5]  21.34 57.58 270 top
R8  0E  [RES0402_0-5]  26.75 57.12 0 top
R9  10K  [RES0402_0-5]  12.57 56.62 0 top
R10  10K  [RES0402_0-5]  83.39 56.12 90 top
R11  10K  [RES0402_0-5]  12.57 54.86 0 top
R12  2.49K_1%  [RES0402_0-5]  136.94 54 270 top
R13  0E  [RES0402_0-5]  138.79 53.98 270 top
R15  10K  [RES0402_0-5]  12.7 53.26 180 top
R16  10K  [RES0402_0-5]  12.68 51.82 180 top
R17  1K  [RES0402_0-5]  25.89 51.82 0 top
R19  10K  [RES0402_0-5]  89.49 50.9 270 top
R20  0E  [RES0402_0-5]  90.94 50.9 270 top
R21  10K  [RES0402_0-5]  92.41 50.9 270 top
R22  11K_1%  [RES0402_0-5]  145.21 50.83 0 top
R23  0E  [RES0402_0-5]  94.21 28.35 0 top
R24  10K  [RES0402_0-5]  35.54 50.55 180 top
R25  0E  [RES0402_0-5]  127.28 50.37 0 top
R26  0E  [RES0402_0-5]  116.44 50.36 0 top
R27  10K  [RES0402_0-5]  12.68 50.32 180 top
R28  1K  [RES0402_0-5]  25.89 50.32 0 top
R29  1K  [RES0402_0-5]  63.75 50.9 0 top
R30  0E  [RES0402_0-5]  65.77 50.04 90 top
R31  0E  [RES0402_0-5]  57.56 51.03 0 top
R32  10K  [RES0402_0-5]  116.44 48.84 180 top
R33  10K  [RES0402_0-5]  12.68 48.82 180 top
R34  1K  [RES0402_0-5]  25.89 48.82 0 top
R35  0E  [RES0406_0-5]  48.87 48.77 180 top
R36  10K  [RES0402_0-5]  69.52 48.46 180 top
R37  10K  [RES0402_0-5]  84.02 48.16 0 top
R39  49.9K_1%  [RES0402_0-5]  87.13 47.7 90 top
R40  10K  [RES0402_0-5]  88.52 47.7 90 top
R41  10K  [RES0402_0-5]  90.68 47.7 90 top
R42  1K  [RES0402_0-5]  92.82 47.7 90 top
R43  10K  [RES0402_0-5]  94.29 47.7 90 top
R44  10K  [RES0402_0-5]  95.81 47.7 90 top
R45  10K  [RES0402_0-5]  97.34 47.7 90 top
R46  0E  [RES0402_0-5]  116.44 47.37 180 top
R47  10K  [RES0402_0-5]  12.68 47.32 180 top
R48  1K  [RES0402_0-5]  25.89 47.32 0 top
R49  0E  [RES0402_0-5]  112.47 46.99 180 top
R50  0E  [RES0402_0-5]  127.36 46.74 0 top
R51  0E  [RES0402_0-5]  133.46 46.62 0 top
R52  10K  [RES0402_0-5]  12.68 45.82 180 top
R53  1K  [RES0402_0-5]  25.89 45.82 0 top
R54  100K_1%  [RES0402_0-5]  69.22 45.77 180 top
R55  1K  [RES0402_0-5]  87.13 45.34 90 top
R56  1K  [RES0402_0-5]  88.52 45.34 90 top
R57  1K  [RES0402_0-5]  89.9 45.34 90 top
R58  1K  [RES0402_0-5]  91.37 45.34 90 top
R59  1K  [RES0402_0-5]  92.84 45.34 90 top
R60  1K  [RES0402_0-5]  94.29 45.34 90 top
R61  1K  [RES0402_0-5]  95.81 45.34 90 top
R62  1K  [RES0402_0-5]  97.34 45.34 90 top
R63  0E  [RES0402_0-5]  84.3 41.63 90 top
R64  2.49K_1%  [RES0402_0-5]  133.48 45.16 180 top
R65  0E  [RES0402_0-5]  83.21 44.83 270 top
R66  10K  [RES0402_0-5]  12.68 44.32 180 top
R67  1K  [RES0402_0-5]  25.89 44.32 0 top
R68  2.49K_1%  [RES0402_0-5]  133.48 43.74 0 top
R69  10K  [RES0402_0-5]  12.68 42.82 180 top
R70  1K  [RES0402_0-5]  25.89 42.82 0 top
R71  2.49K_1%  [RES0402_0-5]  133.2 41.96 270 top
R72  2.49K_1%  [RES0402_0-5]  134.73 41.96 270 top
R73  2.49K_1%  [RES0402_0-5]  136.22 41.96 90 top
R74  2.49K_1%  [RES0402_0-5]  141.79 41.96 270 top
R75  2.49K_1%  [RES0402_0-5]  143.29 41.96 270 top
R76  2.49K_1%  [RES0402_0-5]  145.01 41.96 270 top
R77  100K_1%  [RES0402_0-5]  44.39 41.15 0 top
R78  0E  [RES0402_0-5]  73.72 40.94 270 top
R79  220E  [RES0402_0-5]  5.06 40.77 180 top
R80  453K_1%  [RES0402_0-5]  44.39 39.75 180 top
R81  10K  [RES0402_0-5]  122.48 39.37 0 top
R82  2.2K  [RES0402_0-5]  68.35 38.51 0 top
R83  10K  [RES0402_0-5]  98.63 39.27 270 top
R84  0E  [RES0402_0-5]  40.75 39.04 90 top
R85  10K  [RES0402_0-5]  42.27 39.04 270 top
R86  620E_1%  [RES0402_0-5]  5.06 38.73 180 top
R87  10K  [RES0402_0-5]  72.12 38.35 0 top
R88  2.2K  [RES0402_0-5]  68.35 37.11 0 top
R89  10K  [RES0402_0-5]  64.88 37.59 90 top
R90  10K  [RES0402_0-5]  49.07 36.73 270 top
R91  220E  [RES0402_0-5]  5.06 36.7 180 top
R92  10K  [RES0402_0-5]  11.18 36.32 0 top
R93  620E_1%  [RES0402_0-5]  69.45 35.53 0 top
R94  620E_1%  [RES0402_0-5]  19.43 35.29 270 top
R95  2.49K_1%  [RES0402_0-5]  138.18 34.82 270 top
R96  0E  [RES0406_0-5]  54.59 33.53 180 top
R97  620E_1%  [RES0402_0-5]  69.45 32.64 0 top
R98  1K  [RES0402_0-5]  20.5 31.88 90 top
R99  1K  [RES0402_0-5]  22.05 31.88 90 top
R100  1K  [RES0402_0-5]  23.52 31.88 90 top
R101  1K  [RES0402_0-5]  24.99 31.88 90 top
R102  11K_1%  [RES0402_0-5]  145.21 31.78 0 top
R104  0E  [RES0402_0-5]  9.45 31.45 270 top
R105  10K  [RES0402_0-5]  10.9 31.45 90 top
R106  10K  [RES0402_0-5]  12.34 31.45 90 top
R107  0E  [RES0402_0-5]  13.79 31.45 270 top
R108  10K  [RES0402_0-5]  28.37 30.35 90 top
R109  10K  [RES0402_0-5]  29.84 30.35 90 top
R110  200K  [RES0402_0-5]  14.63 29.72 0 top
R111  220E  [RES0402_0-5]  5.33 29.36 0 top
R112  10K  [RES0402_0-5]  44.17 29.36 90 top
R113  909K_1%  [RES0402_0-5]  14.63 28.17 0 top
R114  220E  [RES0402_0-5]  5.33 27.58 0 top
R115  0E  [RES0402_0-5]  133.46 27.57 0 top
R116  10K  [RES0402_0-5]  39.27 27.28 270 top
R117  3.48K_1%  [RES0402_0-5]  35.46 26.79 0 top
R118  16.5K_1%  [RES0402_0-5]  37.62 26.79 0 top
R119  4.7K  [RES0402_0-5]  14.63 26.72 180 top
R120  4.7K  [RES0402_0-5]  72.22 26.67 0 top
R121  10K  [RES0402_0-5]  64.34 26.31 90 top
R122  10K  [RES0402_0-5]  65.61 26.31 90 top
R123  2.49K_1%  [RES0402_0-5]  133.48 26.12 180 top
R124  100K_1%  [RES0402_0-5]  50.11 25.91 0 top
R125  10K  [RES0402_0-5]  46.53 25.5 180 top
R126  10K  [RES0402_0-5]  72.22 25.4 0 top
R127  0E  [RES0402_0-5]  48.21 25.02 90 top
R128  10K  [RES0402_0-5]  150.47 24.77 0 top
R129  2.49K_1%  [RES0402_0-5]  133.48 24.69 0 top
R130  41.2K_1%  [RES0402_0-5]  50.11 24.51 180 top
R131  0E  [RES0402_0-5]  160.38 23.52 0 top
R132  2.49K_1%  [RES0402_0-5]  133.2 22.91 270 top
R133  2.49K_1%  [RES0402_0-5]  134.73 22.91 270 top
R134  2.49K_1%  [RES0402_0-5]  136.22 22.91 90 top
R135  2.2K  [RES0402_0-5]  140.19 22.91 90 top
R136  2.2K  [RES0402_0-5]  141.66 22.91 90 top
R137  2.49K_1%  [RES0402_0-5]  143.29 22.91 270 top
R138  2.49K_1%  [RES0402_0-5]  144.76 22.91 270 top
R139  2.49K_1%  [RES0402_0-5]  146.59 22.91 270 top
R140  0E  [RES0402_0-5]  150.47 22.89 180 top
R141  0E  [RES0402_0-5]  145.06 20.57 180 top
R142  3.48K_1%  [RES0402_0-5]  42.24 20.29 270 top
R143  2.94K_1%  [RES0402_0-5]  43.61 20.29 90 top
R144  2.94K_1%  [RES0402_0-5]  44.98 20.29 90 top
R145  3.48K_1%  [RES0402_0-5]  46.35 20.29 270 top
R146  2.94K_1%  [RES0402_0-5]  47.73 20.29 90 top
R147  3.48K_1%  [RES0402_0-5]  49.1 20.29 270 top
R148  2.94K_1%  [RES0402_0-5]  50.47 20.29 90 top
R149  3.48K_1%  [RES0402_0-5]  51.84 20.29 270 top
R150  2.94K_1%  [RES0402_0-5]  53.21 20.29 90 top
R151  3.48K_1%  [RES0402_0-5]  54.58 20.29 270 top
R152  2.94K_1%  [RES0402_0-5]  55.96 20.29 90 top
R153  3.48K_1%  [RES0402_0-5]  57.33 20.29 270 top
R154  2.94K_1%  [RES0402_0-5]  58.7 20.29 90 top
R155  3.48K_1%  [RES0402_0-5]  60.07 20.29 270 top
R156  2.94K_1%  [RES0402_0-5]  61.44 20.29 90 top
R157  3.48K_1%  [RES0402_0-5]  62.81 20.29 270 top
R158  0E  [RES0402_0-5]  145.01 19.08 180 top
R159  1M  [RES0603_0-75]  9.27 17.4 90 top
R160  1M  [RES0603_0-75]  25.51 17.4 90 top
R161  0E  [RES0402_0-5]  100.99 16 180 top
R162  22E_1%  [RES0201_0-5]  70.31 15.34 90 top
R163  0E  [RES0402_0-5]  100.99 13.46 0 top
R164  1K  [RES0402_0-5]  65.43 9.68 270 top
R165  10K  [RES0402_0-5]  168.76 62.89 270 bottom
R166  220E  [RES0402_0-5]  165.76 62.89 90 bottom
R167  220E  [RES0402_0-5]  167.34 62.89 90 bottom
R168  220E  [RES0402_0-5]  174.97 63.27 270 bottom
R169  110E  [RES0402_0-5]  173.63 63.27 270 bottom
R170  1K  [RES0402_0-5]  27.61 60.55 270 bottom
R171  1K  [RES0402_0-5]  9.28 60.55 270 bottom
R172  10K  [RES0402_0-5]  166.77 59.34 90 bottom
R173  10K  [RES0402_0-5]  171.47 59.34 90 bottom
R174  10K  [RES0402_0-5]  172.93 58.06 270 bottom
R175  88.7K_1%  [RES0402_0-5]  21.79 58.17 180 bottom
R176  100K_1%  [RES0402_0-5]  21.79 56.72 0 bottom
R177  10K  [RES0402_0-5]  21.77 55.26 0 bottom
R178  2.2K  [RES0402_0-5]  9.17 54.99 180 bottom
R179  0E  [RES0402_0-5]  77.96 54.1 270 bottom
R180  0E  [RES0402_0-5]  76.56 54.1 270 bottom
R181  10K  [RES0402_0-5]  75.16 54.1 90 bottom
R182  2.2K  [RES0402_0-5]  11.58 54.05 180 bottom
R183  10K  [RES0402_0-5]  81.2 54.03 180 bottom
R184  2.49K_1%  [RES0402_0-5]  136.94 54 90 bottom
R185  0E  [RES0402_0-5]  138.79 53.98 270 bottom
R186  2.2K  [RES0402_0-5]  9.17 53.11 180 bottom
R187  2.2K  [RES0402_0-5]  11.58 52.17 180 bottom
R188  10K  [RES0402_0-5]  21.89 52.04 180 bottom
R189  10K  [RES0402_0-5]  9.17 51.23 0 bottom
R190  10K  [RES0402_0-5]  105.69 50.65 90 bottom
R191  10K  [RES0402_0-5]  24.94 50.65 270 bottom
R192  10K  [RES0402_0-5]  91.57 50.47 90 bottom
R193  10K  [RES0402_0-5]  90.1 50.47 90 bottom
R194  10K  [RES0402_0-5]  88.65 50.47 90 bottom
R195  14.7K_1%  [RES0402_0-5]  21.79 49 0 bottom
R196  10K  [RES0402_0-5]  11.58 50.29 0 bottom
R197  10K  [RES0402_0-5]  9.17 49.35 0 bottom
R198  16.9K_1%  [RES0402_0-5]  19.94 49.28 90 bottom
R199  5.23K_1%  [RES0402_0-5]  18.21 49.28 270 bottom
R200  1M  [RES0603_0-75]  172.67 36.94 270 bottom
R201  100K_1%  [RES0402_0-5]  21.79 50.44 0 bottom
R202  10K  [RES0402_0-5]  11.58 48.41 0 bottom
R203  10K  [RES0402_0-5]  97.41 47.68 270 bottom
R204  10K  [RES0402_0-5]  95.86 47.68 270 bottom
R205  49.9K_1%  [RES0402_0-5]  94.31 47.68 270 bottom
R206  49.9K_1%  [RES0402_0-5]  90.68 47.68 270 bottom
R207  10K  [RES0402_0-5]  88.52 47.68 270 bottom
R208  10K  [RES0402_0-5]  87.13 47.68 270 bottom
R209  10K  [RES0402_0-5]  9.17 47.47 0 bottom
R210  220E  [RES0402_0-5]  180.26 56.25 0 bottom
R211  10K  [RES0402_0-5]  11.58 46.53 0 bottom
R212  10K  [RES0402_0-5]  16.82 46.41 180 bottom
R213  0E  [RES0402_0-5]  95.81 45.34 90 bottom
R214  1K  [RES0402_0-5]  94.29 45.34 90 bottom
R215  1K  [RES0402_0-5]  91.37 45.34 90 bottom
R216  1K  [RES0402_0-5]  88.57 45.34 90 bottom
R217  1K  [RES0402_0-5]  87.12 45.31 90 bottom
R218  2.49K_1%  [RES0402_0-5]  133.48 45.16 0 bottom
R219  15K  [RES0402_0-5]  16.82 44.98 0 bottom
R220  220E  [RES0402_0-5]  161.34 37.29 90 bottom
R221  2.49K_1%  [RES0402_0-5]  133.48 43.74 180 bottom
R222  100E_1%  [RES0402_0-5]  16.82 43.41 180 bottom
R223  220E  [RES0402_0-5]  161.34 40.18 90 bottom
R224  10K  [RES0402_0-5]  42.55 42.55 270 bottom
R225  2.49K_1%  [RES0402_0-5]  145.09 41.96 90 bottom
R226  2.49K_1%  [RES0402_0-5]  143.29 41.96 90 bottom
R227  2.49K_1%  [RES0402_0-5]  141.81 41.96 90 bottom
R228  2.49K_1%  [RES0402_0-5]  136.22 41.88 270 bottom
R229  2.49K_1%  [RES0402_0-5]  134.73 41.88 90 bottom
R230  2.49K_1%  [RES0402_0-5]  133.2 41.88 90 bottom
R231  0E  [RES0402_0-5]  16.82 40.94 180 bottom
R232  1.69K_1%  [RES0402_0-5]  127.99 40.87 270 bottom
R233  3.57K_1%  [RES0402_0-5]  126.47 40.87 90 bottom
R234  10K  [RES0402_0-5]  71.63 40.06 180 bottom
R235  2.2K  [RES0402_0-5]  38.9 39.37 270 bottom
R236  10K  [RES0402_0-5]  142.07 38.4 90 bottom
R237  2.2K  [RES0402_0-5]  67.23 37.52 270 bottom
R238  2.2K  [RES0402_0-5]  65.91 37.52 270 bottom
R239  499E_1%  [RES0201_0-5]  86.97 36.35 90 bottom
R240  0E  [RES0402_0-5]  72.24 35.23 180 bottom
R241  10K  [RES0402_0-5]  149.4 35.08 0 bottom
R242  2.49K_1%  [RES0402_0-5]  138.18 34.82 90 bottom
R243  10K  [RES0402_0-5]  160.66 34.21 90 bottom
R244  0E  [RES0402_0-5]  72.21 33.73 180 bottom
R245  10K  [RES0402_0-5]  149.4 33.55 0 bottom
R246  10K  [RES0402_0-5]  16.31 33.43 0 bottom
R247  4.99K_1%  [RES0402_0-5]  127.99 30.15 270 bottom
R248  1.87K_1%  [RES0402_0-5]  126.47 30.15 90 bottom
R249  51E  [RES0402_0-5]  15.35 29.51 90 bottom
R250  10K  [RES0402_0-5]  112.52 28.7 180 bottom
R251  0E  [RES0402_0-5]  2.52 28.19 90 bottom
R252  220E  [RES0402_0-5]  157 27.46 90 bottom
R253  1M  [RES0603_0-75]  174.62 14.44 270 bottom
R254  2.49K_1%  [RES0402_0-5]  133.48 26.11 0 bottom
R255  11K_1%  [RES0402_0-5]  65.07 25.88 0 bottom
R256  4.87K_1%  [RES0402_0-5]  23.39 25.57 0 bottom
R257  220E  [RES0402_0-5]  157 30.73 90 bottom
R258  220E  [RES0402_0-5]  180.27 35.61 0 bottom
R259  0E  [RES0402_0-5]  160.38 21.16 0 bottom
R260  2.49K_1%  [RES0402_0-5]  133.48 24.69 180 bottom
R261  0E  [RES0402_0-5]  86.23 23.27 180 bottom
R262  100K_1%  [RES0402_0-5]  65.07 24.05 180 bottom
R263  0E  [RES0402_0-5]  160.38 23.52 0 bottom
R264  2.49K_1%  [RES0402_0-5]  146.59 22.91 90 bottom
R265  2.49K_1%  [RES0402_0-5]  144.76 22.91 90 bottom
R266  2.49K_1%  [RES0402_0-5]  143.29 22.91 90 bottom
R267  2.49K_1%  [RES0402_0-5]  136.22 22.91 270 bottom
R268  2.49K_1%  [RES0402_0-5]  134.73 22.91 90 bottom
R269  2.49K_1%  [RES0402_0-5]  133.2 22.91 90 bottom
R270  0E  [RES0402_0-5]  164.68 22.66 0 bottom
R271  22E_1%  [RES0201_0-5]  69.47 19.94 0 bottom
R272  49.9K_1%  [RES0402_0-5]  156.51 19.51 270 bottom
R273  49.9K_1%  [RES0402_0-5]  154.79 19.51 270 bottom
R274  49.9K_1%  [RES0402_0-5]  152.98 19.51 270 bottom
R275  10K  [RES0402_0-5]  142.62 19.35 90 bottom
R276  10K  [RES0402_0-5]  161.62 16.56 0 bottom
R277  59E_1%  [RES0402_0-5]  165.76 15.47 180 bottom
R278  59E_1%  [RES0402_0-5]  163.86 15.47 180 bottom
R279  49.9K_1%  [RES0402_0-5]  156.51 13.16 270 bottom
R280  49.9K_1%  [RES0402_0-5]  154.79 13.16 270 bottom
R281  49.9K_1%  [RES0402_0-5]  152.98 13.16 270 bottom
R282  220E  [RES0402_0-5]  175.98 9.63 270 bottom
R283  220E  [RES0402_0-5]  174.48 9.63 270 bottom
R284  220E  [RES0402_0-5]  172.98 9.63 270 bottom
R285  220E  [RES0402_0-5]  171.48 9.63 270 bottom
R286  0E  [RES0402_0-5]  89.53 26.87 0 bottom
R287  0E  [RES0402_0-5]  87.25 31.04 0 bottom
R586  1K  [RES0402_0-5]  96.98 39.65 90 top
R587  1K  [RES0402_0-5]  95.22 40.03 90 top
R588  10K  [RES0402_0-5]  97.21 42.24 90 top
R589  10K  [RES0402_0-5]  96.95 42.39 270 bottom
R590  10K  [RES0402_0-5]  92.61 39.95 270 top
R591  10K  [RES0402_0-5]  92.61 39.95 90 bottom
R592  100K_1%  [RES0402_0-5]  32.93 12.26 180 bottom
R593  1K  [RES0402_0-5]  34.16 14 0 top
R594  0E  [RES0402_0-5]  103.26 31.92 90 bottom
R595  0E  [RES0402_0-5]  103.78 31.39 0 bottom
R596  0E  [RES0402_0-5]  99.95 37.08 90 top
R597  0E  [RES0402_0-5]  100.47 36.56 0 top
SW1  436331045822  [SW4_436331045822_190X190_SMD_1-7]  13.24 63.53 180 top
SW2  436331045822  [SW4_436331045822_190X190_SMD_1-7]  21.92 63.53 180 top
SW3  436331045822  [SW4_436331045822_190X190_SMD_1-7]  30.41 63.53 180 top
SW4  416131160808  [SW16_416131160808_460X230_SMD_2-7]  19.28 46.86 270 top
SW5  436331045822  [SW4_436331045822_190X190_SMD_1-7]  71.68 9.27 0 top
TP1  -  [TP20_SMD]  31.72 55.65 270 top
TP2  THRU HOLE  [TP_40X65]  33.89 54.86 0 top
TP3  THRU HOLE  [TP_40X65]  36.43 54.86 0 top
TP4  -  [TP20_SMD]  142.73 53.85 0 top
TP5  -  [TP40_SMD]  63.78 52.81 180 top
TP6  -  [TP20_SMD]  7.24 48.79 0 top
TP7  -  [TP40_SMD]  55.61 49.15 0 top
TP9  THRU HOLE  [TP_40X65]  36.7 45.19 0 top
TP11  -  [TP20_SMD]  138.79 42.04 0 top
TP12  -  [TP20_SMD]  61.62 40.82 0 top
TP13  -  [TP20_SMD]  71.17 40.01 0 top
TP14  -  [TP20_SMD]  72.42 40.01 0 top
TP15  -  [TP20_SMD]  20.42 39.88 0 top
TP16  -  [TP20_SMD]  21.79 39.88 0 top
TP17  -  [TP20_SMD]  23.16 39.88 0 top
TP18  -  [TP20_SMD]  24.53 39.88 0 top
TP19  -  [TP20_SMD]  61.62 39.57 0 top
TP20  -  [TP40_SMD]  124.64 39.37 270 top
TP21  -  [TP20_SMD]  71.56 36.96 0 top
TP22  -  [TP20_SMD]  72.72 36.96 0 top
TP23  -  [TP40_SMD]  56.54 36.63 0 top
TP24  -  [TP20_SMD]  59.61 36.2 0 top
TP25  -  [TP20_SMD]  142.73 34.8 0 top
TP26  -  [TP20_SMD]  15.85 33.35 0 top
TP27  -  [TP40_SMD]  2.03 31.5 0 top
TP28  -  [TP20_SMD]  7.85 30.96 180 top
TP29  -  [TP20_SMD]  16.26 28.91 180 top
TP30  -  [TP40_SMD]  125.17 28.47 270 top
TP31  -  [TP20_SMD]  74.27 25.43 0 top
TP32  -  [TP40_SMD]  19.94 25.63 0 top
TP33  -  [TP20_SMD]  138.79 22.99 0 top
TP34  -  [TP20_SMD]  159.87 22.12 0 top
TP35  -  [TP40_SMD]  36.45 16.89 0 top
TP36  THRU HOLE  [TP_40X65]  29.31 11.73 0 top
TP37  THRU HOLE  [TP_40X65]  163.58 63.2 0 top
TP38  THRU HOLE  [TP_40X65]  87.48 9.04 0 top
TP39  -  [TP40_SMD]  38.46 22.48 0 top
TP40  -  [TP20_SMD]  35 57.56 0 top
TP41  -  [TP20_SMD]  90.14 27.2 0 top
TP42  -  [TP20_SMD]  70.59 29.34 0 top
TP43  -  [TP20_SMD]  70.13 39.17 0 top
TP44  -  [TP20_SMD]  73.66 26.39 0 top
TP45  -  [TP20_SMD]  90.5 36.12 0 top
TP46  -  [TP20_SMD]  72.69 31.14 0 top
TP47  -  [TP20_SMD]  93.42 33.73 0 top
TP48  -  [TP20_SMD]  80.54 41.83 0 top
TP49  -  [TP20_SMD]  7.82 41.55 0 top
TP50  -  [TP20_SMD]  164.82 22.56 0 top
TP51  -  [TP20_SMD]  55.88 40.06 0 top
TP52  -  [TP20_SMD]  84.51 23.16 0 top
TP53  -  [TP40_SMD]  26.44 24.41 0 top
U1  SN74LVC1G11DCKR  [SC70-6]  29.82 57.94 0 top
U2  S25HL512TFAMHI010  [SOIC16_W_2-7]  76.69 51.18 180 top
U3  25.000MHz  [OSC4_ASEK_130X100_SMD_1-2]  113.08 49.56 0 top
U4  SN74AVC8T245RHL  [QFN24_19-68_220X140_1]  31.09 49.4 270 top
U5  TPS7A2518DRVR  [SON6_25-59_85X85_0-8]  60.94 48.9 180 top
U6  LMK1C1103PWR  [TSSOP8_25-59_125X180_1-2]  121.77 48.51 0 top
U7  DP83869HMRGZT  [QFN48_19-68_280X280_1_EP4-2]  139.93 48.08 180 top
U8  SN74CB3Q3125PWR  [TSSOP14_25-59_205X180_1-2]  104.67 47.88 180 top
U9  TCA9617BDGKR  [VSSOP8_25-59_120X120_1-1]  7.35 44.83 180 top
U10  TPS62822DLCT  [VSONHR8_TPS62823_60X80_1]  44.18 43.43 90 top
U11  SN74LV1T34DCKR  [SC70-5_1-1]  76.32 41.02 0 top
U12  SN74CB3Q3125PWR  [TSSOP14_25-59_205X180_1-2]  104.67 41.02 180 top
U13  SN74LVC3G17DCUR  [VSSOP8_19-68_85X95_0-9]  59.51 40.15 90 top
U14  TLV75518PDBVR  [SOT23-5_1-5]  52.6 37.77 0 top
U15  SN74AHC1G02DRLR  [SOT553-5_0-6]  14.35 35.56 0 top
U16  TXS0102DCUR  [VSSOP8_19-68_85X95_0-9]  29.18 34.39 180 top
U17  AT24CM01  [TSSOP8_25-59_125X180_1-2]  64.37 31.88 90 top
U18  XAM2434ASFGGAALX  [BGA293_19-68_440X440_1]  81.89 30.86 90 top
U19  DP83869HMRGZT  [QFN48_19-68_280X280_1_EP4-2]  139.93 29.03 180 top
U20  TUSB320LAIRWBR  [X2QFN12_TUSB322I_60X60_0-4]  11.72 28.39 90 top
U21  TPS62822DLCT  [VSONHR8_TPS62823_60X80_1]  49.89 28.19 90 top
U22  TMUX154EDGSR  [MSOP10_19-68_120X120_1-1]  155.55 23.77 0 top
U23  TPS22965DSGT  [WSON8_19-68_80X80_0-8]  30.94 22.94 0 top
U24  TPD4E02B04DQAR  [USON10_TPD4E05U_40X100_0-6]  8.62 22.16 0 top
U25  SN74AVC4T245PW  [TSSOP16_25-59_205X180]  70.36 20.19 90 top
U26  TCA6408ARGTR  [QFN16_19-68_120X120_1_EP1-6]  25.82 54.51 270 bottom
U27  TPS386000RGPR  [QFN20_19-68_160X160_1]  16.74 54.08 270 bottom
U28  SN74LVC1G08DBVRE4  [SOT23-5]  36.81 51.44 180 bottom
U30  TMUX154EDGSR  [MSOP10_19-68_120X120_1-1]  101.02 50.55 180 bottom
U31  SN74LVC1G08DBVRE4  [SOT23-5]  76.69 50.55 270 bottom
U32  TXB0106PWR  [TSSOP16_25-59_205X180]  121.79 48.84 0 bottom
U33  TPS74801DRCR  [VSON10_TPS74801-Q1_120X120_1]  123.55 41.51 0 bottom
U34  SN74LVC1G08DBVRE4  [SOT23-5]  139.4 39.17 90 bottom
U35  TPIC2810D  [SOIC16_1-8]  155.17 38.1 180 bottom
U36  LM4040B25IDCKR  [SC70-5_1-1]  41.4 38.48 0 bottom
U37  TM4C1294NCPDTT3R  [TQFP128_15-74_550X550_1-2]  26.9 35.69 180 bottom
U38  TPS74633PQWDRVRQ1  [SON6_25-59_85X85_0-8]  13.06 32 180 bottom
U39  TPS74801DRCR  [VSON10_TPS74801-Q1_120X120_1]  123.55 30.79 0 bottom
U40  TS3DDR3812RUAR  [TQFN42_19-68_140X360_0-8]  108 29.34 180 bottom
U41  TPS7A0533PDBVT  [SOT23-5_1-5#2]  6.84 28.58 0 bottom
U42  SN74AVC2T244DQMR  [X2SON8_15-74_70X50]  67.08 20.37 180 bottom
U43  SN74LVC1G08DBVRE4  [SOT23-5]  139.95 19.61 90 bottom
U44  TCAN1044VDRBRQ1  [SON8_25-59_130X130_1]  164.85 18.77 270 bottom
U45  SN74AVC4T245PW  [TSSOP16_25-59_205X180]  33.96 17.35 90 bottom
U46  TXB0106RGYR  [QFN16_19-68_160X140_1]  142.98 13.72 90 bottom
Y1  16.000MHz  [XTAL4_LFXTAL055474_130X110_SMD_0-8]  12.3 38.99 270 bottom

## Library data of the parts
C1-C82 C84-C86 C88 C90-C114 C116-C126 C128-C163 C165-C194 C196-C260 C262 C263 C265-C270 = CAP
D1 D2 D4-D8 = DIODE_TVS_DUAL
D3 = DIODE_ZENER_SOT23_13
FB1-FB9 = INDUCTOR_FERRITE
FL1 = EMIFILTER_IND
J1 J2 J5 J6 = RECP_10X2
J9 J11 J14 = HEADER_3X1
J10 = CON_USB-C_24_6327233
J12 J21 = HEADER_5X1
J13 J17 = HEADER_6X1
J15 = CON_FLEX_40X1_20347
J16 = HEADER_5X2
J18 J19 = CON_RJ45-14_LPJG16314A4NL
J20 = CON_USB_MINI-B
J22 = HEADER_2X1
L1 L2 = INDUCTOR
L3 = INDUCTOR_DLW31S
LD1 LD2 LD6-LD15 = DIODE_LED
LD3 = LED4_150066RV54050
Q3-Q6 Q9-Q15 = MOSFET_CSD17313Q2
Q7 Q8 Q16 = MOSFET_CSD25310Q2
R1-R6 R8-R13 R15-R17 R19 R21 R22 R24-R37 R39-R50 R52-R62 R64-R102 R104-R114 R116-R285 R586-R594 R596 = RESISTOR
R20 R23 R51 R63 R115 R286 R287 R595 R597 = RESISTOR: signal model: RESISTOR_RES0402_0-5_0E_0E
SW1-SW3 SW5 = SW4_EVQP
SW4 = SW16_CHS-08A
TP1-TP7 TP9 TP11-TP53 = TESTPOINT
U1 = SN74LVC1G11DCKR_SC70-6
U2 = S25HL512TFAMHI01_SOIC16
U3 = OSC4_EQXP-HC33
U4 = SN74AVC8T245RHL_QFN24
U5 = TPS7A2518_WSON6
U6 = LMK1C1103_TSSOP8
U7 U19 = DP83869HM_VQFN48
U8 U12 = SN74CBTLV3125PWR_TSSOP14
U9 = TCA9617BDGKR_VSSOP8
U10 U21 = TPS62823_VSONHR8
U11 = SN74LVC1G07DBVR_SOT23-5
U13 = SN74LVC3G17DCUR_VSSOP8
U14 U41 = TLV71318PDBVT_SOT23-5
U15 = SN74AHC1G02DBV_SOT23-5
U16 = TXS0102DCUR_VSSOP8
U17 = AT24HC04B-TH-B_TSSOP8
U18 = AM243X SOC_LP_EVM_BGA293
U20 = TUSB320LAI_X2QFN12
U22 U30 = TMUX154EDGSR_VSSOP10
U23 = TPS22965DSGT_WSON8
U24 = TPD4E02B04DQAR_USON10
U25 U45 = SN74AVC4T245PW_TSSOP16
U26 = TCA6408ARGTR_VQFN16
U27 = TPS386000RGPR_QFN20
U28 U31 U34 U43 = SN74LVC1G08DBVRE4_SOT23-5
U32 = TXB0106PWR_TSSOP16
U33 U39 = TPS74801DRCR_SON10
U35 = TPIC2810D_SOIC16
U36 = LM4040B25IDCKR_SC70-5
U37 = TM4C1294NCPDTT3R_TQFP128
U38 = TPS74618_WSON6
U40 = TS3DDR3812RUAR_WQFN42
U42 = SN74AVC2T244DQMR_X2SON8
U44 = TCAN1044V-Q1_SON8
U46 = TXB0106RGYR_VQFN16
Y1 = CRY4_13

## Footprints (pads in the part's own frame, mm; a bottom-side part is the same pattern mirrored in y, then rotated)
BGA293_19-68_440X440_1
  round 0.254 smd: A1(-5,5) A2(-4.5,5) A3(-4,5) A5(-3,5) A6(-2.5,5) A8(-1.5,5) A9(-1,5) A11(0,5) A12(0.5,5) A14(1.5,5) A15(2,5) A17(3,5) A18(3.5,5) A20(4.5,5) A21(5,5) AA1(-5,-5) AA2(-4.5,-5) AA4(-3.5,-5) AA5(-3,-5) AA7(-2,-5) AA8(-1.5,-5) AA10(-0.5,-5) AA11(0,-5) AA13(1,-5) AA14(1.5,-5) AA16(2.5,-5) AA17(3,-5) AA19(4,-5) AA20(4.5,-5) AA21(5,-5) B1(-5,4.5) B2(-4.5,4.5) B3(-4,4.5) B4(-3.5,4.5) B5(-3,4.5) B6(-2.5,4.5) B7(-2,4.5) B8(-1.5,4.5) B9(-1,4.5) B10(-0.5,4.5) B11(0,4.5) B12(0.5,4.5) B13(1,4.5) B14(1.5,4.5) B15(2,4.5) B16(2.5,4.5) B17(3,4.5) B18(3.5,4.5) B19(4,4.5) B20(4.5,4.5) B21(5,4.5) C2(-4.5,4) C5(-3,4) C6(-2.5,4) C9(-1,4) C11(0,4) C13(1,4) C16(2.5,4) C17(3,4) C20(4.5,4) C21(5,4) D1(-5,3.5) D2(-4.5,3.5) D4(-3.5,3.5) D6(-2.5,3.5) D9(-1,3.5) D10(-0.5,3.5) D12(0.5,3.5) D13(1,3.5) D16(2.5,3.5) D17(3,3.5) D18(3.5,3.5) D20(4.5,3.5) E1(-5,3) E2(-4.5,3) E3(-4,3) E4(-3.5,3) E6(-2.5,3) E7(-2,3) E8(-1.5,3) E9(-1,3) E11(0,3) E13(1,3) E14(1.5,3) E15(2,3) E16(2.5,3) E19(4,3) E20(4.5,3) E21(5,3) F2(-4.5,2.5) F3(-4,2.5) F4(-3.5,2.5) F5(-3,2.5) F8(-1.5,2.5) F11(0,2.5) F14(1.5,2.5) F17(3,2.5) F18(3.5,2.5) F19(4,2.5) F20(4.5,2.5) F21(5,2.5) G1(-5,2) G2(-4.5,2) G5(-3,2) G6(-2.5,2) G9(-1,2) G10(-0.5,2) G11(0,2) G12(0.5,2) G13(1,2) G16(2.5,2) G17(3,2) G20(4.5,2) H1(-5,1.5) H2(-4.5,1.5) H5(-3,1.5) H6(-2.5,1.5) H7(-2,1.5) H8(-1.5,1.5) H11(0,1.5) H14(1.5,1.5) H15(2,1.5) H16(2.5,1.5) H17(3,1.5) H20(4.5,1.5) H21(5,1.5) J2(-4.5,1) J3(-4,1) J4(-3.5,1) J5(-3,1) J6(-2.5,1) J9(-1,1) J10(-0.5,1) J11(0,1) J12(0.5,1) J13(1,1) J16(2.5,1) J17(3,1) J18(3.5,1) J19(4,1) J20(4.5,1) J21(5,1) K1(-5,0.5) K2(-4.5,0.5) K4(-3.5,0.5) K6(-2.5,0.5) K7(-2,0.5) K8(-1.5,0.5) K11(0,0.5) K14(1.5,0.5) K15(2,0.5) K16(2.5,0.5) K18(3.5,0.5) K20(4.5,0.5) L1(-5,0) L2(-4.5,0) L3(-4,0) L5(-3,0) L6(-2.5,0) L9(-1,0) L10(-0.5,0) L11(0,0) L12(0.5,0) L13(1,0) L16(2.5,0) L17(3,0) L19(4,0) L20(4.5,0) L21(5,0) M2(-4.5,-0.5) M4(-3.5,-0.5) M6(-2.5,-0.5) M7(-2,-0.5) M8(-1.5,-0.5) M11(0,-0.5) M14(1.5,-0.5) M15(2,-0.5) M16(2.5,-0.5) M18(3.5,-0.5) M20(4.5,-0.5) M21(5,-0.5) N1(-5,-1) N2(-4.5,-1) N3(-4,-1) N4(-3.5,-1) N5(-3,-1) N6(-2.5,-1) N9(-1,-1) N10(-0.5,-1) N11(0,-1) N12(0.5,-1) N13(1,-1) N16(2.5,-1) N17(3,-1) N18(3.5,-1) N19(4,-1) N20(4.5,-1) P1(-5,-1.5) P2(-4.5,-1.5) P5(-3,-1.5) P6(-2.5,-1.5) P7(-2,-1.5) P8(-1.5,-1.5) P11(0,-1.5) P14(1.5,-1.5) P15(2,-1.5) P16(2.5,-1.5) P17(3,-1.5) P20(4.5,-1.5) P21(5,-1.5) R2(-4.5,-2) R5(-3,-2) R6(-2.5,-2) R9(-1,-2) R10(-0.5,-2) R11(0,-2) R12(0.5,-2) R13(1,-2) R16(2.5,-2) R17(3,-2) R20(4.5,-2) R21(5,-2) T1(-5,-2.5) T2(-4.5,-2.5) T3(-4,-2.5) T4(-3.5,-2.5) T5(-3,-2.5) T8(-1.5,-2.5) T11(0,-2.5) T14(1.5,-2.5) T17(3,-2.5) T18(3.5,-2.5) T19(4,-2.5) T20(4.5,-2.5) U1(-5,-3) U2(-4.5,-3) U3(-4,-3) U6(-2.5,-3) U7(-2,-3) U8(-1.5,-3) U9(-1,-3) U11(0,-3) U13(1,-3) U14(1.5,-3) U15(2,-3) U16(2.5,-3) U18(3.5,-3) U19(4,-3) U20(4.5,-3) U21(5,-3) V2(-4.5,-3.5) V4(-3.5,-3.5) V5(-3,-3.5) V6(-2.5,-3.5) V9(-1,-3.5) V10(-0.5,-3.5) V12(0.5,-3.5) V13(1,-3.5) V16(2.5,-3.5) V18(3.5,-3.5) V20(4.5,-3.5) V21(5,-3.5) W1(-5,-4) W2(-4.5,-4) W5(-3,-4) W6(-2.5,-4) W9(-1,-4) W11(0,-4) W13(1,-4) W16(2.5,-4) W17(3,-4) W20(4.5,-4) Y1(-5,-4.5) Y2(-4.5,-4.5) Y3(-4,-4.5) Y4(-3.5,-4.5) Y5(-3,-4.5) Y6(-2.5,-4.5) Y7(-2,-4.5) Y8(-1.5,-4.5) Y9(-1,-4.5) Y10(-0.5,-4.5) Y11(0,-4.5) Y12(0.5,-4.5) Y13(1,-4.5) Y14(1.5,-4.5) Y15(2,-4.5) Y16(2.5,-4.5) Y17(3,-4.5) Y18(3.5,-4.5) Y19(4,-4.5) Y20(4.5,-4.5) Y21(5,-4.5)
CAP0201_0-5
  rect 0.356x0.33 smd: 1(-0.28,0) 2(0.28,0)
CAP0402_0-75
  rect 0.559x0.635 smd: 1(-0.49,0) 2(0.49,0)
CAP0603_1
  rect 0.711x0.889 smd: 1(-0.7,0) 2(0.7,0)
CAP1206_2
  rect 0.991x1.702 smd: 1(-1.35,0) 2(1.35,0)
CAP1210_1-5
  rect 0.965x2.718 smd: 1(-1.65,0) 2(1.65,0)
CON_FLEX1X40_687140183622_S_R_S_1-3
  rect 0.305x1.041 smd: 1(-9.75,2.405) 2(-9.25,2.405) 3(-8.75,2.405) 4(-8.25,2.405) 5(-7.75,2.405) 6(-7.25,2.405) 7(-6.75,2.405) 8(-6.25,2.405) 9(-5.75,2.405) 10(-5.25,2.405) 11(-4.75,2.405) 12(-4.25,2.405) 13(-3.75,2.405) 14(-3.25,2.405) 15(-2.75,2.405) 16(-2.25,2.405) 17(-1.75,2.405) 18(-1.25,2.405) 19(-0.75,2.405) 20(-0.25,2.405) 21(0.25,2.405) 22(0.75,2.405) 23(1.25,2.405) 24(1.75,2.405) 25(2.25,2.405) 26(2.75,2.405) 27(3.25,2.405) 28(3.75,2.405) 29(4.25,2.405) 30(4.75,2.405) 31(5.25,2.405) 32(5.75,2.405) 33(6.25,2.405) 34(6.75,2.405) 35(7.25,2.405) 36(7.75,2.405) 37(8.25,2.405) 38(8.75,2.405) 39(9.25,2.405) 40(9.75,2.405)
  rect 1.753x1.397 smd: 41(-12.025,0.505) 42(12.025,0.505)
CON_MUSBB5_629105150521_S_R_S_2-7
  round 0.686 hole 0.813 unplated: (-2.5,1.848) (2.5,1.848)
  rect 0.457x1.295 smd: 1(-1.3,2.948) 2(-0.65,2.948) 3(0,2.948) 4(0.65,2.948) 5(1.3,2.948)
  oval 1.448x2.311 hole 0.864x1.727: 6(-3.725,2.898) 7(3.725,2.898)
  oval 1.143x1.803 hole 0.559x1.219: 8(-3.875,-0.902) 9(3.875,-0.902)
CON_RJ45-14_LPJG16314A4NL_S_R_T_13-6
  round 3.073 hole 3.2 unplated: (0,-8.89) (11.43,-8.89)
  rect 1.6x1.6 hole 0.914: 1(0,0)
  round 1.6 hole 0.914: 2(1.27,-2.54) 3(2.54,0) 4(3.81,-2.54) 5(5.08,0) 6(6.35,-2.54) 7(7.62,0) 8(8.89,-2.54) 9(10.16,0) 10(11.43,-2.54)
  round 1.702 hole 1.016: 11(12.44,-11.43) 12(12.44,-13.462) 13(-1.01,-11.43) 14(-1.01,-13.462)
  round 2.362 hole 1.676: 15(-2.032,-5.842) 16(13.462,-5.842)
CON_USBC24_6327233_S_R_S_3-1
  rect 0.305x1.194 smd: A1(-2.75,5.815) A2(-2.25,5.815) A3(-1.75,5.815) A4(-1.25,5.815) A5(-0.75,5.815) A6(-0.25,5.815) A7(0.25,5.815) A8(0.75,5.815) A9(1.25,5.815) A10(1.75,5.815) A11(2.25,5.815) A12(2.75,5.815)
  round 0.66 hole 0.406: B1(2.8,4.565) B2(2.4,3.865) B3(1.6,3.865) B4(1.2,4.565) B5(0.8,3.865) B6(0.4,4.565) B7(-0.4,4.565) B8(-0.8,3.865) B9(-1.2,4.565) B10(-1.6,3.865) B11(-2.4,3.865) B12(-2.8,4.565) G1(-2,4.565) G2(2,4.565)
  oval 0.991x1.6 hole 0.61x1.219: SH1(-4.27,3.415) SH2(4.27,3.415) SH3(-4.27,-1.315) SH4(4.27,-1.315)
  rect 0.203x0.991 smd: SH5(0,1.235) SH6(0,-1.865)
DIO_DFN0201_0-4
  rect 0.229x0.381 smd: 1(-0.22,0) 2(0.22,0)
DIO_SMB_2-7
  rect 2.261x2.159 smd: 1(-2.2,0) 2(2.2,0)
EMIFIL_BLM18B_0603_0-7
  rect 1.194x1.092 smd: 1(-0.85,0) 2(0.85,0)
HDR_1X2_61300211121_S_T_8-6
  rect 1.803x1.803 hole 1.118: 1(0,0)
  round 1.803 hole 1.118: 2(-2.54,0)
HDR_1X3_100_S_T
  rect 1.803x1.803 hole 1.118: 1(0,0)
  round 1.803 hole 1.118: 2(-2.54,0) 3(-5.08,0)
HDR_1X5_61300511121_S_T_8-6
  rect 1.803x1.803 hole 1.118: 1(0,0)
  round 1.803 hole 1.118: 2(-2.54,0) 3(-5.08,0) 4(-7.62,0) 5(-10.16,0)
HDR_1X6_61300611121_S_T_8-6
  rect 1.803x1.803 hole 1.118: 1(0,0)
  round 1.803 hole 1.118: 2(-2.54,0) 3(-5.08,0) 4(-7.62,0) 5(-10.16,0) 6(-12.7,0)
HDR_2X5_61301021121_S_T_8-6
  rect 1.803x1.803 hole 1.118: 1(0,0)
  round 1.803 hole 1.118: 2(0,2.54) 3(2.54,0) 4(2.54,2.54) 5(5.08,0) 6(5.08,2.54) 7(7.62,0) 8(7.62,2.54) 9(10.16,0) 10(10.16,2.54)
IND4_DLW21H_90X60_SMD_1-4
  rect 0.889x0.356 smd: 1(-0.85,-0.425) 2(0.85,-0.425) 3(0.85,0.425) 4(-0.85,0.425)
IND0603_1
  rect 0.914x1.016 smd: 1(-0.8,0) 2(0.8,0)
IND0603_1#2
  rect 1.245x1.092 smd: 1(-0.85,0) 2(0.85,0)
IND0806_1-2
  rect 1.219x1.803 smd: 1(-0.85,0) 2(0.85,0)
LED4_150066RV54050_70X60_SMD_0-7
  rect 0.787x0.508 smd: 1(-0.8,-0.45) 2(0.8,-0.45) 3(0.8,0.45) 4(-0.8,0.45)
LED_150040GS73220_40X20_SMD_0-4
  rect 0.406x0.457 smd: 1(-0.5,0) 2(0.5,0)
LED_150060SS75000_70X40_SMD_0-8
  rect 0.787x0.787 smd: 1(-0.8,0) 2(0.8,0)
MSOP10_19-68_120X120_1-1
  rect 1.448x0.305 smd: 1(-2.2,1) 2(-2.2,0.5) 3(-2.2,0) 4(-2.2,-0.5) 5(-2.2,-1) 6(2.2,-1) 7(2.2,-0.5) 8(2.2,0) 9(2.2,0.5) 10(2.2,1)
OSC4_ASEK_130X100_SMD_1-2
  rect 1.397x0.991 smd: 1(-1.1,-0.8) 2(1.1,-0.8) 3(1.1,0.8) 4(-1.1,0.8)
QFN16_19-68_120X120_1_EP1-6
  rect 0.838x0.254 smd: 1(-1.45,0.75) 2(-1.45,0.25) 3(-1.45,-0.25) 4(-1.45,-0.75) 9(1.45,-0.75) 10(1.45,-0.25) 11(1.45,0.25) 12(1.45,0.75)
  rect 0.254x0.838 smd: 5(-0.75,-1.45) 6(-0.25,-1.45) 7(0.25,-1.45) 8(0.75,-1.45) 13(0.75,1.45) 14(0.25,1.45) 15(-0.25,1.45) 16(-0.75,1.45)
  rect 1.6x1.6 smd: 17(0,0)
QFN16_19-68_160X140_1
  rect 0.864x0.279 smd: 1(-1.975,-0.75) 8(1.975,-0.75) 9(1.975,0.75) 16(-1.975,0.75)
  rect 0.279x0.864 smd: 2(-1.25,-1.725) 3(-0.75,-1.725) 4(-0.25,-1.725) 5(0.25,-1.725) 6(0.75,-1.725) 7(1.25,-1.725) 10(1.25,1.725) 11(0.75,1.725) 12(0.25,1.725) 13(-0.25,1.725) 14(-0.75,1.725) 15(-1.25,1.725)
  rect 2.54x2.057 smd: 17(0,0)
